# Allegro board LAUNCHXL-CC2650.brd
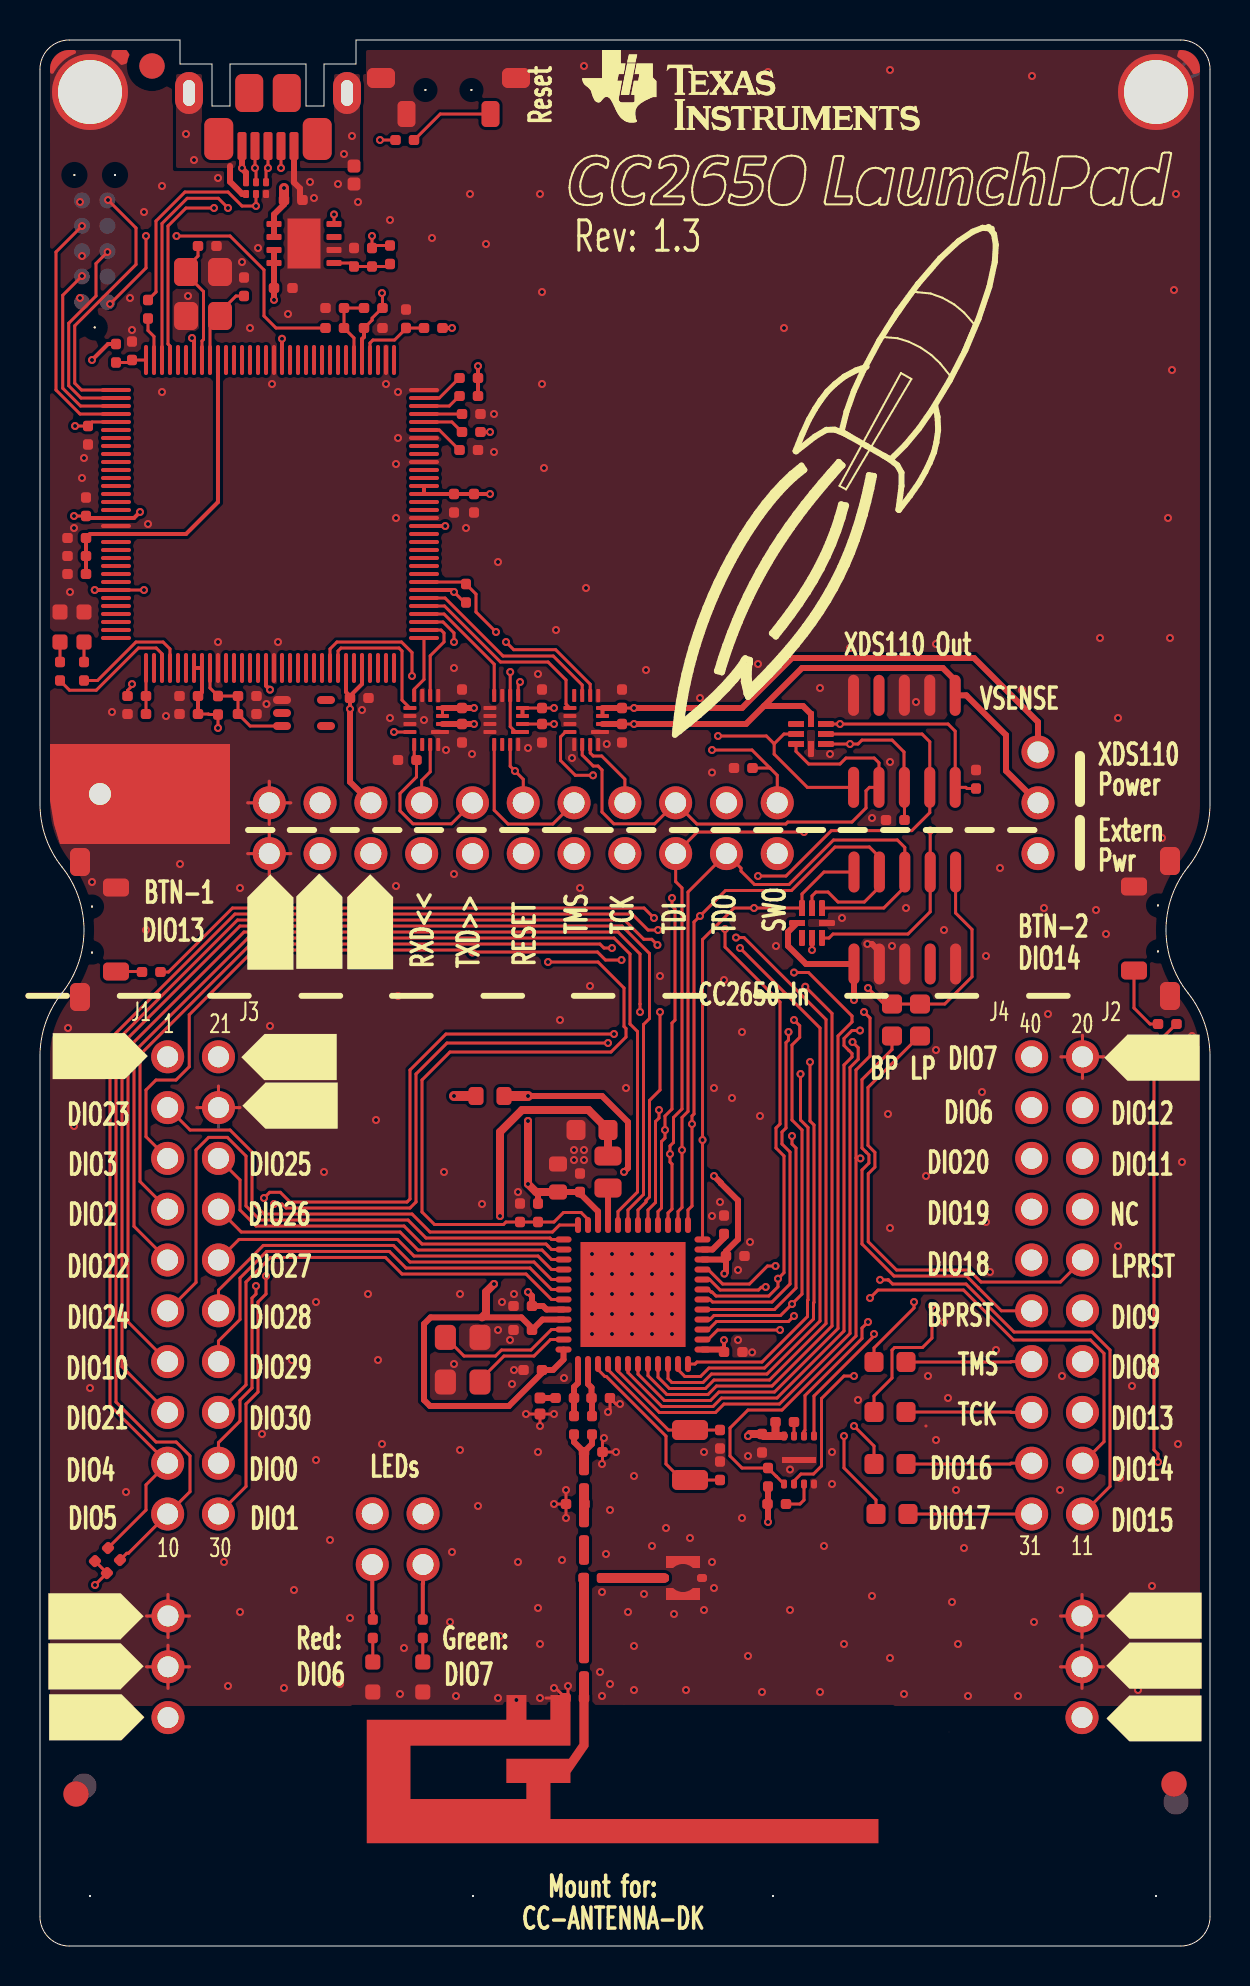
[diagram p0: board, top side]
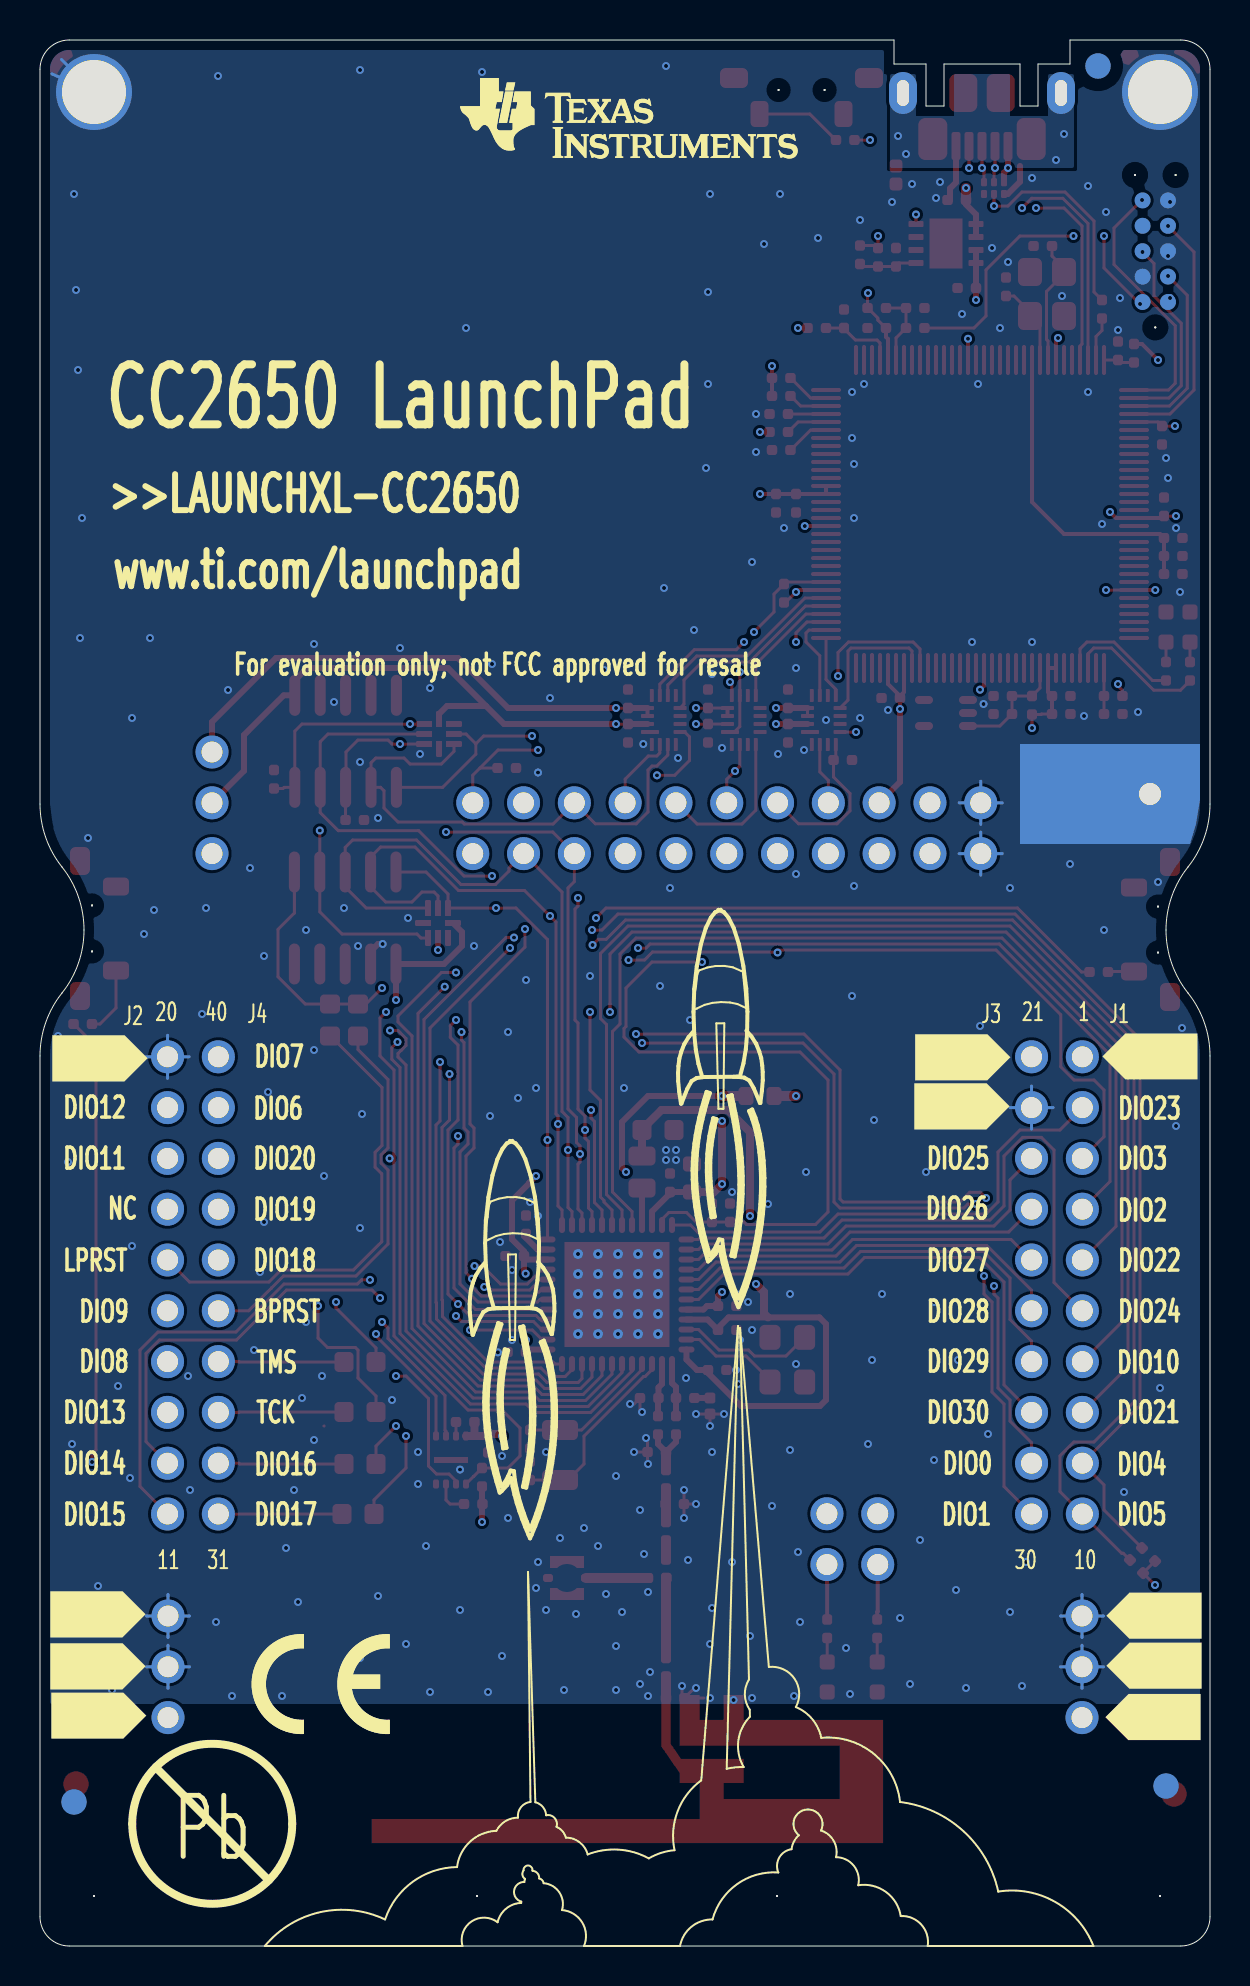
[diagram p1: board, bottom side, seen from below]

Outline 58.5 x 95.3 mm; copper layers: TOP, L2, L3, BOTTOM. Coordinates in mm from the lower left corner of the outline.
Outline path: 0,93.84 0,57.1 arc(0.28,55.43) 1.1,53.95 arc(1.92,52.47) 2.2,50.8 arc(1.92,49.13) 1.1,47.65 arc(0.28,46.17) 0,44.5 0,1.46 arc(0.43,0.43) 1.46,0 57.04,0 arc(58.07,0.43) 58.5,1.46 58.5,44.5 arc(58.22,46.17) 57.4,47.65 arc(56.58,49.13) 56.3,50.8 arc(56.58,52.47) 57.4,53.95 arc(58.22,55.43) 58.5,57.1 58.5,93.84 arc(58.07,94.87) 57.04,95.3 15.8,95.3 15.8,94.1 14.2,94.1 14.2,92 13.3,92 13.3,94.1 9.5,94.1 9.5,92 8.6,92 8.6,94.1 7,94.1 7,95.3 1.46,95.3 arc(0.43,94.87) 0,93.84

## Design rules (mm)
nets with their own width: min track width 0.15; nets CC2650_VDD GND V-SENSE VDDR VDDS XDS_VCC
nets with their own width: min track width 0.3; nets +5V

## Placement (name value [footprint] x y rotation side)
A1  2.4GHz  [ANTENNA_DN007AN]  27.2 12.3 180 top
C3  100nF  [CAPC1005X60B2N]  34.2 29.7 0 top
C4  100nF  [CAPC1005X60B2N]  34.3 34.5 0 top
C5  100nF  [CAPC1005X60B2N]  24.6 32 180 top
C6  10uF  [CAPC1608X90N#2]  25.9 37.7 90 top
C7  100nF  [CAPC1005X60B2N]  27 37.7 90 top
C8  10uF  [CAPC1608X90N]  28.4 40.8 180 top
C9  100nF  [CAPC1005X60B2N]  25.1 28.8 180 top
C11  1pF  [CAPC1005X60B2N]  26.7 26.5 270 top
C12  DNM_0402  [CAPC1005X60B2N]  27.2 24.7 0 top
C13  1pF  [CAPC1005X60B2N]  26.3 22.1 0 top
C15  DNM_0402  [CAPC1005X60B2N]  27.2 12.4 180 top
C16  100nF  [CAPC1005X60B2N]  24.6 30.8 180 top
C17  12pF  [CAPC1005X60B2N]  34 23.3 90 top
C18  12pF  [CAPC1005X60B2N]  34 25.8 270 top
C19  1uF  [CAPC1005X60B2N]  34.2 35.6 90 top
C20  100nF  [CAPC1005X60B2N]  24 36.2 90 top
C21  1pF  [CAPC1005X60B2N]  28.5 27.4 180 top
C24  12pF  [CAPC1005X60B2N]  27.2 18.4 90 top
C30  100nF  [CAPC1005X60B2N]  36.1 25.6 270 top
C31  6.8pF  [CAPC1005X60N]  25 27.4 270 top
C32  100nF  [CAPC1005X60B2N]  9.9 62.5 0 top
C33  12pF  [CAPC1005X60B2N]  10.2 82.5 90 top
C34  12pF  [CAPC1005X60B2N]  7.9 85 0 top
C35  10nF  [CAPC1005X60B2N]  15.5 62.4 0 top
C36  10nF  [CAPC1005X60B2N]  2.3 71.5 90 top
C37  10nF  [CAPC1005X60B2N]  2.4 76 270 top
C38  100nF  [CAPC1005X60B2N]  16.2 80.9 0 top
C39  100nF  [CAPC1005X60B2N]  20.7 72.6 270 top
C40  1uF  [CAPC1005X60B2N]  21.7 72.6 270 top
C41  10nF  [CAPC1005X60B2N]  7.9 62.5 180 top
C42  1uF  [CAPC1005X60B2N]  7.9 61.6 180 top
C43  100nF  [CAPC1005X60B2N]  2.3 70.4 180 top
C44  1uF  [CAPC1005X60B2N]  2.3 69.5 180 top
C45  2.2uF  [CAPC1005X60B2N]  2.3 68.6 180 top
C46  100nF  [CAPC1005X60B2N]  18.3 80.9 90 top
C47  15pF  [CAPC1005X60B2N]  16.6 84.9 270 top
C48  2.2uF  [CAPC1005X60B2N]  12.2 87.3 0 top
C49  2.2uF  [CAPC1005X60B2N]  11.7 82.9 0 top
C50  10nF  [CAPC1005X60B2N]  9.9 61.6 0 top
C51  1.8pF  [CAPC1005X60B2N]  27.2 14.4 270 top
C52  100nF  [CAPC1005X60B2N]  21.1 61.9 90 top
C53  100nF  [CAPC1005X60B2N]  21.1 61.1 270 top
C54  100nF  [CAPC1005X60B2N]  25.1 61.9 90 top
C55  100nF  [CAPC1005X60B2N]  25.1 61.1 270 top
C56  100nF  [CAPC1005X60B2N]  29.1 61.9 90 top
C57  100nF  [CAPC1005X60B2N]  29.1 61.1 270 top
C58  DNM_0402  [CAPC1005X60B2N]  28.1 18.4 180 top
C59  10nF  [CAPC1005X60B2N]  4.6 79.3 90 top
CR1  LPL296-J2L2-25  [LEDC1707X65L]  19.14 12.7 90 top
CR2  LS L296-P2Q2-1  [LEDC1708X67L]  16.64 12.7 90 top
CR4  LS L296-P2Q2-1  [LEDC1708X67L]  1 66.7 270 top
CR5  LPL296-J2L2-25  [LEDC1707X65L]  2.2 66.7 270 top
CR6  TPD4E004DRY  [SON50P100X145X60-6N]  10.3 87.6 0 top
CR7  TPD6E004RSER  [QFN50P150X150X60-8N]  37.8 61.1 270 top
CR8  TPD6E004RSER  [QFN50P150X150X60-8N]  38.1 50.4 0 top
FIDU1  FIDU_1.27mm  [FID127X142]  5.6 94 0 top
FIDU2  FIDU_1.27mm  [FID127X142]  1.8 7.6 0 top
FIDU3  FIDU_1.27mm  [FID127X142]  56.7 8.1 0 top
FIDU4  FIDU_1.27mm  [FID127X142]  5.6 94 180 bottom
FIDU5  FIDU_1.27mm  [FID127X142]  2.2 8 180 bottom
FIDU6  FIDU_1.27mm  [FID127X142]  56.8 7.2 180 bottom
FL1  BLM18HE152SN1  [FIL_BLM18HE152SN1DL]  23.2 42.5 180 top
J1  SSQ-110-23-L-D  [SAMTEC_SSQ11023LD_A2B]  6.38 44.46 0 bottom
J2  SSQ-110-23-L-D  [SAMTEC_SSQ11023LD_A2B]  49.58 44.46 0 bottom
J6  105164-0001  [MOLEX_1051640001_A2N]  10.1 90 0 top
L1  10uH  [INDC2012X150L]  28.4 37.9 90 top
L11  2.4nH  [INDC1005X60B2N]  26.7 27.4 180 top
L12  2nH  [INDC1005X60B2N]  27.2 23.8 270 top
L13  2nH  [INDC1005X60B2N]  27.2 21.2 270 top
L21  2.4nH  [INDC1005X60B2N]  27.6 26.5 270 top
LBL1  NON_COMPONENT_LABEL_8mm  [LABEL_PB-FREE_8MM_A2N]  54.1 1.9 180 bottom
LBL2  CE_label  [CE_LABEL]  45.3 10.6 180 bottom
MH1  HOLE_3.2mm_NPL  [MTG320]  2.5 2.5 0 top
MH2  HOLE_3.2mm_NPL  [MTG320]  55.8 2.5 0 top
MH3  HOLE_3.2mm_PTH  [MTG320_380]  2.5 92.7 0 top
MH4  HOLE_3.2mm_PTH  [MTG320_380]  55.8 92.7 0 top
MH5  HOLE_1.1mm_PTH  [MTG110_170]  3 57.6 0 top
NOREF  -  []  -1.9 11.6 0 top
NOREF#2  -  []  0 79.15 0 top
NOREF#3  #VALUE  [unnamed#2]  21.65 2.5 0 top
NOREF#4  -  []  51.6 11.6 0 top
NOREF#5  -  []  8.4 39.6 0 top
NOREF#6  -  []  -2 8.9 0 top
NOREF#7  -  []  8.4 41.9 0 top
NOREF#8  -  []  -1.9 14.1 0 top
NOREF#9  -  []  51.5 42 0 top
NOREF#10  -  []  40.01 0 90 top
NOREF#11  -  []  -4.3 43.3 0 top
NOREF#12  -  []  53.1 10 0 top
NOREF#13  -  []  16.5 46.4 90 top
NOREF#14  -  []  13.9 46.5 90 top
NOREF#15  -  []  17.7 43.9 90 top
NOREF#16  -  []  51.6 14.1 0 top
NOREF#17  -  []  60.3 14.2 180 bottom
NOREF#18  -  []  6.9 8.9 180 bottom
NOREF#19  -  []  58 10.3 180 bottom
NOREF#20  -  []  6.9 11.6 180 bottom
NOREF#21  -  []  51.53 65.52 180 bottom
NOREF#22  -  []  6.9 14.1 180 bottom
NOREF#23  -  []  5.6 43.1 180 bottom
NOREF#24  -  []  17.2 41.9 180 bottom
NOREF#25  -  []  60.2 42 180 bottom
NOREF#26  -  []  17.1 39.6 180 bottom
NOREF#27  -  []  60.3 11.6 180 bottom
P1  BB02-HC031-KB1-603000  [GRADCONN_BB02HC031KB1603000_A2B]  52.1 11.42 90 top
P2  BB02-HC031-KB1-603000  [GRADCONN_BB02HC031KB1603000_A2B]  6.4 11.42 90 top
P4  BB02-HJ221-KB1-603000  [GRADCONN_BB02HJ221KB160300_A2B]  36.86 57.16 180 top
P5  FTSH-105-01-F-DV-K  [SAMTEC_FTSH-105-01-F-DV-K-10L]  40.7 49.1 0 top
P6  BB02-HJ041-KB1-603000  [GRADCONN_BB02HJ041KB1603000_A2B]  16.61 19.07 0 top
P7  FTSH-105-01-F-DV-K  [SAMTEC_FTSH-105-01-F-DV-K-10L]  45.76 62.53 180 top
P8  TC2050-IDC-NL  [TAGCONNECT_TC2050IDCNLN]  2.1 82.2 90 bottom
P10  BB02-HC031-KB1-603000  [GRADCONN_BB02HC031KB1603000_A2B]  49.9 59.7 270 top
P11  MM5829-2700  [MURATA_MM58292700RJ4_A2N]  31.2 18.4 0 top
R1  100k  [RESC1005X40B2N]  24.9 36.2 90 top
R2  3.3k  [RESC1005X40B2N]  3.4 19.9 225 top
R3  3.3k  [RESC1005X40B2N]  4 19.3 225 top
R11  2.2k  [RESC1005X40B2N]  36.4 23.9 270 top
R14  220  [RESC1005X40B2N]  16.64 15.4 90 top
R15  180  [RESC1005X40B2N]  19.14 15.4 90 top
R17  10k  [RESC1005X40B2N]  16.2 81.9 0 top
R18  4.7k  [RESC1005X40B2N]  8.9 62.5 270 top
R20  100  [RESC1005X40B2N]  15.2 80.9 180 top
R21  DNM  [RESC1005X40B2N]  15.2 81.9 180 top
R22  330k  [RESC1005X40B2N]  5.3 62.5 180 top
R23  180  [RESC1005X40B2N]  1 64.2 270 top
R24  220k  [RESC1005X40B2N]  5.3 61.6 180 top
R25  220  [RESC1005X40B2N]  2.2 64.2 270 top
R27  1k  [RESC1005X40B2N]  21.9 77.5 180 top
R28  4.87k  [RESC1005X40B2N]  21.9 74.8 180 top
R29  1k  [RESC1005X40B2N]  21.1 76.6 0 top
R30  1k  [RESC1005X40B2N]  21.1 75.7 0 top
R31  51  [RESC1005X40B2N]  19.2 80.9 0 top
R32  33k  [RESC1005X40N]  15.7 88.1 90 top
R33  51k  [RESC1005X40B2N]  17.5 84.1 90 top
R34  30k  [RESC1005X40B2N]  15.7 84.9 270 top
R39  1k  [RESC1005X40B2N]  21.9 78.4 180 top
R46  DNM  [RESC1608X55N]  43.3 29.2 180 top
R47  DNM  [RESC1608X55N]  43.3 26.7 180 top
R48  DNM  [RESC1608X55N]  43.3 24.1 180 top
R49  DNM  [RESC1608X55N]  43.4 21.6 180 top
R51  DNM  [RESC1608X55N]  44 45.5 90 top
R52  0  [RESC1608X55N]  42.6 47.1 270 top
R55  100  [RESC1005X40B2N]  55.9 46.1 0 top
R56  100  [RESC1005X40B2N]  5.1 48.7 0 top
R57  100  [RESC1005X40B2N]  18.7 90.3 180 top
R58  3.3k  [RESC1005X40B2N]  21.3 68.1 270 top
R59  DNM  [RESC1005X40B2N]  37.3 22.1 180 top
R60  DNM  [RESC1005X40B2N]  37.7 26.2 180 top
R61  100k  [RESC1005X40B2N]  17.9 59.3 0 top
R62  100k  [RESC1005X40B2N]  34.7 58.9 0 top
R63  100k  [RESC1005X40B2N]  42.3 56.3 0 top
R65  100k  [RESC1005X40B2N]  46.8 58.8 270 top
R66  100  [RESC1005X40B2N]  3.8 80.1 270 top
R67  DNM  [RESC1005X40B2N]  5.4 82.3 270 top
SW1  1188E-1K2-V  [SW_1188E1K2V_A2N]  2 54.2 270 top
SW2  1188E-1K2-V  [SW_1188E1K2V_A2N]  56.5 47.5 90 top
SW3  1188E-1K2-V  [SW_1188E1K2V_A2N]  23.8 93.4 180 top
U1  CC2650F128RGZ  [QFNFC50P700X700X80-49CL]  26.9 29.1 0 top
U4  MX25R8035FZUIL0  [SON50P300X200X60-9B2L]  37.2 23.1 0 top
U5  TM4C1294NCPDTT3R  [QFP40P1600X1600X120-128N]  5.3 63.9 0 top
U6  LM4040B25IDCK  [SOT65P210X110-5N]  12.1 62.3 270 top
U7  TPS79601DR  [SON65P300X300X100-9AL]  11.7 86.1 270 top
U8  SN74AVC4T245RSV  [QFNFC40P180X260X55-16A2L]  20 60.7 90 top
U9  SN74AVC4T245RSV  [QFNFC40P180X260X55-16A2L]  28 60.7 90 top
U10  SN74AVC4T245RSV  [QFNFC40P180X260X55-16A2L]  24 60.7 90 top
UNK#REFDES  -  []  28.1 94.8 0 top
UNK#REFDES#2  -  []  36.5 93.4 180 bottom
Y1  32.768kHz  [XTAL_FC-135N]  32.5 23.3 90 top
Y2  24MHz  [OSCCC250X320X60-4L]  22 28.2 90 top
Y3  16MHz  [OSCCC250X320X100-4BN]  9 81.5 90 top

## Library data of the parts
A1 = ANTENNA_DN007
C3-C5 C7 C9 C11-C13 C15-C21 C24 C30 C32-C50 C52-C59 = CAPACITOR: User Part Number: #PN
C6 C8 = CAPACITOR: alternate symbols: (CAPC1608X90L,CAPC1608X90M)
C31 = CAPACITOR: alternate symbols: (CAPC1005X60L,CAPC1005X60M)
C51 = CAPACITOR_HOR: User Part Number: #PN
CR1 CR5 = LED: alternate symbols: (LEDC1707X65L,LEDC1707X65M)
CR2 CR4 = LED: alternate symbols: (LEDC1708X67L,LEDC1708X67M)
CR6 = DIODE_TPD4E004_SON6: User Part Number: #PN; alternate symbols: (SON50P100X145X65-6L,SON50P100X145X65-6M)
CR7 CR8 = DIODE_TVS_TPD6E004_QFN8_V1_0: alternate symbols: (QFN50P150X150X60-8L,QFN50P150X150X60-8M,QFN50P150X150X60-8AL)
FIDU1-FIDU6 = FIDMARK
FL1 = FILTER_2PIN: alternate symbols: (FIL_BLM18HE152SN1DL,FIL_BLM18HE152SN1DM)
J1 J2 = CONN_HEADER_2X10_J_S_V1: User Part Number: #PN; alternate symbols: (SAMTEC_SSQ11023LD_A2C,SAMTEC_SSQ11023LD_A2A)
J6 = CONN_USB_MICRO_B_2MH: User Part Number: #PN; alternate symbols: (MOLEX_1051640001_A2L,MOLEX_1051640001_A2M)
L1 = INDUCTOR: alternate symbols: (INDC2012X150L,INDC2012X150M)
L11-L13 L21 = INDUCTOR: User Part Number: #PN
LBL1 = LABEL_Pb-free_V1: User Part Number: #PN
LBL2 = CE_LABEL
MH1 MH2 = HOLE_NPL
MH3-MH5 = HOLE_PTH
NOREF#3 = -: User Part Number: #PN
P1 P2 P10 = CONN_HEADER_3_P_S: User Part Number: #PN; alternate symbols: (GRADCONN_BB02HC031KB1603000_A2C,GRADCONN_BB02HC031KB1603000_A2A)
P4 = CONN_HEADER_2X11_P_S: User Part Number: #PN; alternate symbols: (GRADCONN_BB02HJ221KB160300_A2C,GRADCONN_BB02HJ221KB160300_A2A)
P5 P7 = CONN_HEADER_2X5: alternate symbols: (SAMTEC_FTSH-105-01-F-DV-K-10L,SAMTEC_FTSH-105-01-F-DV-K-10M)
P6 = CONN_HEADER_2X2_P: User Part Number: #PN; alternate symbols: (GRADCONN_BB02HJ041KB1603000_A2C,GRADCONN_BB02HJ041KB1603000_A2A)
P8 = CONN_IDC_TC2050-IDC-NL: User Part Number: #PN; alternate symbols: (TAGCONNECT_TC2050IDCNLL,TAGCONNECT_TC2050IDCNLM)
P11 = CONN_COAX_1_1_P_2MH_V1: User Part Number: #PN; alternate symbols: (MURATA_MM58292700RJ4_A2L,MURATA_MM58292700RJ4_A2M)
R1-R3 R11 R14 R15 R17 R18 R20-R25 R27-R31 R33 R34 R39 R55-R63 R65-R67 = RESISTOR: User Part Number: #PN
R32 = RESISTOR: alternate symbols: (RESC1005X40L,RESC1005X40M)
R46-R49 R51 R52 = RESISTOR: alternate symbols: (RESC1608X55L,RESC1608X55M)
SW1-SW3 = SWITCH_TACT_V2: alternate symbols: (SW_1188E1K2V_A2L,SW_1188E1K2V_A2M)
U1 = IC_RF_CC26XX_QFN48_V2: alternate symbols: (QFNFC50P700X700X80-49CL,QFNFC50P700X700X80-49CM)
U4 = IC_FLASH_MX25R8035F_USON8: User Part Number: #PN; alternate symbols: (SON50P300X200X60-9B2L,SON50P300X200X60-9B2M)
U5 = IC_PROC_TM4C1294NCPDT_TQFP128: alternate symbols: (QFP40P1600X1600X120-128L,QFP40P1600X1600X120-128M)
U6 = IC_REF_LM4040_SC70-5: alternate symbols: (SOT65P210X110-5L,SOT65P210X110-5M)
U7 = IC_PM_TPS79601_SON8: alternate symbols: (SON65P300X300X100-9AL,SON65P300X300X100-9AM)
U8-U10 = IC_XCVR_SN74AVC4T245_UQFN16_2: User Part Number: #PN; alternate symbols: (QFNFC40P180X260X55-16A2L,QFNFC40P180X260X55-16A2M)
Y1 = CRYSTAL: alternate symbols: (XTAL_FC-135L,XTAL_FC-135M)
Y2 = XTAL_4PIN_S: alternate symbols: (OSCCC250X320X60-4L,OSCCC250X320X60-4M)
Y3 = XTAL_4: alternate symbols: (OSCCC250X320X100-4BL,OSCCC250X320X100-4BM)

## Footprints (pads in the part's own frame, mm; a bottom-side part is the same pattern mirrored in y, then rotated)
ANTENNA_DN007AN
  rect 0.46x0.5 smd: 1(0,0)
  rect 1.001x0.5 smd: 2(1.18,0) 3(3.38,0)
CAPC1005X60B2N
  custom 0.125x0.125 smd: 1(0,0) 2(0.924,0)
CAPC1005X60N
  custom 0.135x0.135 smd: 1(0,0) 2(0.8,0)
CAPC1608X90N
  custom 0.237x0.237 smd: 1(0,0) 2(1.6,0)
CAPC1608X90N#2
  custom 0.188x0.188 smd: 1(0,0) 2(1.4,0)
CE_LABEL
  oval 0.025x0.051 smd: 1(-0.15,0.1)
FID127X142
  round 1.27 smd: 1(0,0)
FIL_BLM18HE152SN1DL
  custom 0.188x0.188 smd: 1(0,0) 2(1.4,0)
GRADCONN_BB02HC031KB1603000_A2B
  round 1.65 hole 1.05: 1(0,0) 2(2.54,0) 3(5.08,0)
GRADCONN_BB02HJ041KB1603000_A2B
  round 1.65 hole 1.05: 1(0,0) 2(0,2.54) 3(2.54,0) 4(2.54,2.54)
GRADCONN_BB02HJ221KB160300_A2B
  round 1.65 hole 1.05: 1(0,0) 2(0,2.54) 3(2.54,0) 4(2.54,2.54) 5(5.08,0) 6(5.08,2.54) 7(7.62,0) 8(7.62,2.54) 9(10.16,0) 10(10.16,2.54) 11(12.7,0) 12(12.7,2.54) 13(15.24,0) 14(15.24,2.54) 15(17.78,0) 16(17.78,2.54) 17(20.32,0) 18(20.32,2.54) 19(22.86,0) 20(22.86,2.54) 21(25.4,0) 22(25.4,2.54)
INDC1005X60B2N
  custom 0.125x0.125 smd: 1(0,0) 2(0.924,0)
INDC2012X150L
  custom 0.237x0.237 smd: 1(0,0) 2(1.6,0)
LEDC1707X65L
  custom 0.188x0.188 smd: 1(0,0) 2(1.501,0)
LEDC1708X67L
  custom 0.188x0.188 smd: 1(0,0) 2(1.501,0)
MOLEX_1051640001_A2N
  custom 0.362x0.362 smd: (-1.162,0.35) (3.762,0.35)
  custom 0.35x0.35 smd: (0.362,2.65) (2.238,2.65)
  custom 0.113x0.113 smd: 1(0,0) 2(0.65,0) 3(1.3,0) 4(1.95,0) 5(2.6,0)
  oval 1.4x2.1 hole 0.6x1.3: M1(-2.65,2.65) M2(5.25,2.65)
MTG110_170
  round 1.699 hole 1.1: 1(0,0)
MTG320
  round 0.099 hole 3.2 unplated: (0,0)
MTG320_380
  round 3.8 hole 3.2: 1(0,0)
MURATA_MM58292700RJ4_A2N
  custom 0.1x0.1 smd: 1(0,0) 2(1.9,0)
  custom 0.15x0.15 smd: M1(0.95,-0.8) M2(0.95,0.8)
OSCCC250X320X60-4L
  custom 0.263x0.263 smd: 1(0,0) 2(2.23,0) 3(2.23,1.73) 4(0,1.73)
OSCCC250X320X100-4BN
  custom 0.299x0.299 smd: 1(0,0) 2(2.2,0) 3(2.2,1.699) 4(0,1.699)
QFN50P150X150X60-8N
  custom 0.075x0.075 smd: 1(0,0) 2(0.5,0) 3(1,0) 4(1.25,0.75) 5(1,1.5) 6(0.5,1.5) 7(0,1.5) 8(-0.25,0.75)
QFNFC40P180X260X55-16A2L
  custom 0.05x0.05 smd: 1(0,0) 2(0.4,-0.125) 3(0.8,-0.125) 4(1.2,-0.125) 5(1.825,0.09) 6(1.825,0.49) 7(1.825,0.89) 8(1.825,1.29) 9(1.2,1.505) 10(0.8,1.505) 11(0.4,1.505) 12(0,1.505) 13(-0.625,1.29) 14(-0.625,0.89) 15(-0.625,0.49) 16(-0.625,0.09)
QFNFC50P700X700X80-49CL
  oval 0.3x0.8 smd: 1(0,0) 2(0.5,0) 3(1.001,0) 4(1.501,0) 5(1.999,0) 6(2.499,0) 7(3,0) 8(3.5,0) 9(4,0) 10(4.501,0) 11(5.001,0) 12(5.499,0) 25(5.499,6.949) 26(5.001,6.949) 27(4.501,6.949) 28(4,6.949) 29(3.5,6.949) 30(3,6.949) 31(2.499,6.949) 32(1.999,6.949) 33(1.501,6.949) 34(1.001,6.949) 35(0.5,6.949) 36(0,6.949)
  oval 0.8x0.3 smd: 13(6.226,0.724) 14(6.226,1.224) 15(6.226,1.725) 16(6.226,2.225) 17(6.226,2.725) 18(6.226,3.226) 19(6.226,3.726) 20(6.226,4.224) 21(6.226,4.724) 22(6.226,5.225) 23(6.226,5.725) 24(6.226,6.226) 37(-0.724,6.226) 38(-0.724,5.725) 39(-0.724,5.225) 40(-0.724,4.724) 41(-0.724,4.224) 42(-0.724,3.726) 43(-0.724,3.226) 44(-0.724,2.725) 45(-0.724,2.225) 46(-0.724,1.725) 47(-0.724,1.224) 48(-0.724,0.724)
  rect 5.25x5.25 smd: 49(2.751,3.475)
QFP40P1600X1600X120-128N
  oval 0.201x1.501 smd: 1(0,0) 2(0.399,0) 3(0.8,0) 4(1.199,0) 5(1.6,0) 6(1.999,0) 7(2.4,0) 8(2.799,0) 9(3.2,0) 10(3.599,0) 11(4,0) 12(4.399,0) 13(4.801,0) 14(5.199,0) 15(5.601,0) 16(6,0) 17(6.401,0) 18(6.8,0) 19(7.201,0) 20(7.6,0) 21(8.001,0) 22(8.4,0) 23(8.801,0) 24(9.2,0) 25(9.601,0) 26(10,0) 27(10.399,0) 28(10.8,0) 29(11.199,0) 30(11.6,0) 31(11.999,0) 32(12.4,0) 65(12.4,15.4) 66(11.999,15.4) 67(11.6,15.4) 68(11.199,15.4) 69(10.8,15.4) 70(10.399,15.4) 71(10,15.4) 72(9.601,15.4) 73(9.2,15.4) 74(8.801,15.4) 75(8.4,15.4) 76(8.001,15.4) 77(7.6,15.4) 78(7.201,15.4) 79(6.8,15.4) 80(6.401,15.4) 81(6,15.4) 82(5.601,15.4) 83(5.199,15.4) 84(4.801,15.4) 85(4.399,15.4) 86(4,15.4) 87(3.599,15.4) 88(3.2,15.4) 89(2.799,15.4) 90(2.4,15.4) 91(1.999,15.4) 92(1.6,15.4) 93(1.199,15.4) 94(0.8,15.4) 95(0.399,15.4) 96(0,15.4)
  oval 1.501x0.201 smd: 33(13.899,1.501) 34(13.899,1.9) 35(13.899,2.301) 36(13.899,2.7) 37(13.899,3.099) 38(13.899,3.5) 39(13.899,3.899) 40(13.899,4.3) 41(13.899,4.699) 42(13.899,5.1) 43(13.899,5.499) 44(13.899,5.9) 45(13.899,6.299) 46(13.899,6.7) 47(13.899,7.099) 48(13.899,7.501) 49(13.899,7.899) 50(13.899,8.301) 51(13.899,8.7) 52(13.899,9.101) 53(13.899,9.5) 54(13.899,9.901) 55(13.899,10.3) 56(13.899,10.701) 57(13.899,11.1) 58(13.899,11.501) 59(13.899,11.9) 60(13.899,12.301) 61(13.899,12.7) 62(13.899,13.099) 63(13.899,13.5) 64(13.899,13.899) 97(-1.501,13.899) 98(-1.501,13.5) 99(-1.501,13.099) 100(-1.501,12.7) 101(-1.501,12.301) 102(-1.501,11.9) 103(-1.501,11.501) 104(-1.501,11.1) 105(-1.501,10.701) 106(-1.501,10.3) 107(-1.501,9.901) 108(-1.501,9.5) 109(-1.501,9.101) 110(-1.501,8.7) 111(-1.501,8.301) 112(-1.501,7.899) 113(-1.501,7.501) 114(-1.501,7.099) 115(-1.501,6.7) 116(-1.501,6.299) 117(-1.501,5.9) 118(-1.501,5.499) 119(-1.501,5.1) 120(-1.501,4.699) 121(-1.501,4.3) 122(-1.501,3.899) 123(-1.501,3.5) 124(-1.501,3.099) 125(-1.501,2.7) 126(-1.501,2.301) 127(-1.501,1.9) 128(-1.501,1.501)
RESC1005X40B2N
  custom 0.125x0.125 smd: 1(0,0) 2(0.924,0)
RESC1005X40N
  custom 0.16x0.16 smd: 1(0,0) 2(0.899,0)
RESC1608X55N
  custom 0.237x0.237 smd: 1(0,0) 2(1.6,0)
SAMTEC_FTSH-105-01-F-DV-K-10L
  oval 0.551x2.05 smd: 1(0,0) 2(0,4.6) 3(1.27,0) 4(1.27,4.6) 5(2.54,0) 6(2.54,4.6) 7(3.81,0) 8(3.81,4.6) 9(5.08,0) 10(5.08,4.6)
SAMTEC_SSQ11023LD_A2B
  round 1.65 hole 1.05: 1(0,0) 2(2.54,0) 3(0,2.54) 4(2.54,2.54) 5(0,5.08) 6(2.54,5.08) 7(0,7.62) 8(2.54,7.62) 9(0,10.16) 10(2.54,10.16) 11(0,12.7) 12(2.54,12.7) 13(0,15.24) 14(2.54,15.24) 15(0,17.78) 16(2.54,17.78) 17(0,20.32) 18(2.54,20.32) 19(0,22.86) 20(2.54,22.86)
SON50P100X145X60-6N
  custom 0.075x0.075 smd: 1(0,0) 2(0.5,0) 3(1.001,0) 4(1.001,0.589) 5(0.5,0.589) 6(0,0.589)
SON50P300X200X60-9B2L
  custom 0.075x0.075 smd: 1(0,0) 2(0.5,0) 3(1,0) 4(1.5,0) 5(1.5,2.4) 6(1,2.4) 7(0.5,2.4) 8(0,2.4)
  rect 1.7x0.3 smd: 9(0.75,1.2)
SON65P300X300X100-9AL
  custom 0.075x0.075 smd: 1(0,0) 2(0.65,0) 3(1.3,0) 4(1.95,0) 5(1.95,3) 6(1.3,3) 7(0.65,3) 8(0,3)
  rect 2.5x1.65 smd: 9(0.975,1.5)
SOT65P210X110-5N
  oval 0.399x0.899 smd: 1(0,0) 2(0.65,0) 3(1.3,0) 4(1.3,2.2) 5(0,2.2)
SW_1188E1K2V_A2N
  round 0.099 hole 0.899 unplated: (2.229,0.6) (4.529,0.6)
  custom 0.25x0.25 smd: 1(0,0) 2(6.75,0)
  custom 0.225x0.225 smd: 3(1.275,1.8) 4(5.475,1.8)
TAGCONNECT_TC2050IDCNLN
  round 0.099 hole 1.001 unplated: (-1.27,0.635) (6.35,-0.38) (6.35,1.65)
  round 0.8 smd: 1(0,0) 2(1.27,0) 3(2.54,0) 4(3.81,0) 5(5.08,0) 6(5.08,1.27) 7(3.81,1.27) 8(2.54,1.27) 9(1.27,1.27) 10(0,1.27)
unnamed#2
  round 0.099 hole 3.2 unplated: (0,0) (15,0)
XTAL_FC-135N
  custom 0.25x0.25 smd: 1(0,0) 2(2.499,0)

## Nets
+5V: J1.2 P2.1 P4.20
GND: A1.2(GND_2) A1.3(GND_3) C3.2 C4.2 C5.2 C6.2 C7.2 C8.2 C9.2 C12.2 C13.1 C15.2 C16.2 C17.2 C18.2 C19.2 C20.2 C21.1 C30.2 C31.2 C32.2 C33.2 C34.2 C35.2 C36.2 C37.2 C38.2 C39.2 C40.2 C41.2 C42.2 C43.2 C44.2 C45.2 C46.2 C48.2 C49.2 C50.2 C52.2 C53.2 C54.2 C55.2 C56.2 C57.2 C59.2 CR1.1(C) CR2.1(C) CR4.1(C) CR5.1(C) CR6.3 CR7.4(GND) CR8.4(GND) J1.4 J2.2 J6.5(GND) MH3.1 MH4.1 MH5.1 P1.2 P1.3 P2.2 P2.3 P4.21 P4.22 P5.3 P5.5 P5.9 P7.3 P7.5 P7.9 P8.3(7) P8.5(8) P8.9(10) P11.2 P11.M1 P11.M2 R21.2 R24.2 R28.1 R29.2 R32.1 R34.1 R61.1 R62.1 R63.1 R65.1 SW1.1 SW1.2 SW1.3 SW2.1 SW2.2 SW2.4 SW3.1 SW3.2 SW3.4 U1.49(VSS) U4.4(GND) U4.9(EGP) U5.10(GNDA) U5.17(GND#17) U5.48(GND#48) U5.55(GND#55) U5.58(GND#58) U5.64(NWAKE) U5.66(XOSC0) U5.80(GND#80) U5.114(GND#114) U6.1(ANODE) U7.6(GND) U7.9(GND/TAB) U8.1(1NOE) U8.5(2DIR) U8.7(1A2) U8.10(GND#10) U8.11(GND#11) U8.16(2NOE) U9.1(1NOE) U9.5(2DIR) U9.10(GND#10) U9.11(GND#11) U9.13(2B1) U9.16(2NOE) U10.7(1A2) U10.9(2A2) U10.10(GND#10) U10.11(GND#11) U10.12(2B2) U10.16(2NOE) Y2.2 Y2.4 Y3.2(GND) Y3.4(NC_4)
VDDC: C43.1 C44.1 C45.1 U5.87(VDDC#87) U5.115(VDDC#115)
VDDR: C8.1 C9.1 C16.1 L1.2 U1.45(VDDR#45) U1.48(VDDR#48)
VDDS: C3.1 C4.1 C5.1 C6.1 C7.1 FL1.1 R1.2 U1.13(VDDS2) U1.22(VDDS3) U1.34(VDDS_DCDC) U1.44(VDDS)
BP_RESET: J2.11 R52.2
CC2650_RESET: C20.1 CR8.2(IO2) P4.12 P5.10 R1.1 R51.2 R52.1 U1.35(RESET_N)
CC2650_RXD: J1.7 P4.16 U1.7(DIO_2)
CC2650_SWO: J2.9 P4.2 U1.28(DIO_18)
CC2650_TCK: CR8.6(IO5) P4.8 P5.4 R47.2 U1.25(JTAG_TCKC)
CC2650_TMS: CR8.7(IO6) P4.10 P5.2 R46.2 U1.24(JTAG_TMSC)
CC2650_TXD: J1.5 P4.14 U1.8(DIO_3)
CC2650_VDD: C30.1 CR8.8(VCC) FL1.2 J1.1 P1.1 P4.18 P5.1 P10.3 R2.2 R3.2 R11.2 R59.2 R60.2 U4.8(VCC)
DCDC_SW: L1.1 U1.33(DCDC_SW)
DIO0: J1.18 U1.5(DIO_0)
DIO1: J1.20 U1.6(DIO_1)
DIO4_SCL: J1.17 R2.1 U1.9(DIO_4)
DIO5_SDA: J1.19 R3.1 U1.10(DIO_5)
DIO6_RLED: J2.3 P6.2 U1.11(DIO_6)
DIO7_GLED: J2.1 P6.4 U1.12(DIO_7)
DIO8_MISO: J2.14 U1.14(DIO_8) U4.2(SO/SIO1)
DIO9_MOSI: J2.12 U1.15(DIO_9) U4.5(SI/SIO0)
DIO10_SCLK: J1.13 U1.16(DIO_10) U4.6(SCLK)
DIO11_CS: J2.6 U1.17(DIO_11)
DIO12: J2.4 U1.18(DIO_12)
DIO13_BTN1: J2.16 R56.2 U1.19(DIO_13)
DIO14_BTN2: J2.18 R55.2 U1.20(DIO_14)
DIO15: J2.20 U1.21(DIO_15)
DIO16_TDO: CR8.5(IO4) P4.4 P5.6 R48.2 U1.26(DIO_16)
DIO17_TDI: CR8.3(IO3) P4.6 P5.8 R49.2 U1.27(DIO_17)
DIO19_CTS: J2.7 U1.29(DIO_19)
DIO20_FLASH_CS: J2.5 R11.1 U1.30(DIO_20) U4.1(NCS)
DIO21: J1.15 U1.31(DIO_21)
DIO22: J1.9 U1.32(DIO_22)
DIO23_ANALOG: J1.3 U1.36(DIO_23)
DIO24_ANALOG: J1.11 U1.37(DIO_24)
DIO25_ANALOG: J1.6 U1.38(DIO_25)
DIO26_ANALOG: J1.8 U1.39(DIO_26)
DIO27_ANALOG: J1.10 U1.40(DIO_27)
DIO28_ANALOG: J1.12 U1.41(DIO_28)
DIO29_ANALOG: J1.14 U1.42(DIO_29)
DIO30_ANALOG: J1.16 U1.43(DIO_30)
IRSTN: P8.10(5) R20.2
ITCK: P8.4(2) U5.100(PC0/TCK/SWCLK)
ITDI: P8.8(4) U5.98(PC2/TDI)
ITDO: P8.6(3) U5.97(PC3/TDO/SWO)
ITMS: P8.2(1) U5.99(PC1/TMS/SWDIO)
LP_RESET: J2.10 R51.1
USB_DM: CR6.5 J6.2(D-) U5.93(PL7/USB0DM)
USB_DP: CR6.4 J6.3(D+) U5.94(PL6/USB0DP)
USB_ID: CR6.2 J6.4(ID) R67.1
USB_VBUS: C48.1 CR6.6 J6.1(VCC) P4.19 R22.2 R66.1 U7.1(IN#1) U7.2(IN#2) U7.8(EN)
V-SENSE: C53.1 C55.1 C57.1 CR7.8(VCC) P7.1 P10.2 U8.2(VCCB) U9.2(VCCB) U10.2(VCCB)
XDS_RESET: R58.1 U5.40(PA6) U10.1(1NOE) U10.6(1A1)
XDS_RESET_LS: CR7.2(IO2) P4.11 P7.10 R57.2 U10.15(1B1)
XDS_RX: U5.33(PA0/U0RX) U8.8(2A1)
XDS_RX_LS: P4.13 R61.2 U8.13(2B1)
XDS_SWO: U5.25(PC4/C1-) U8.9(2A2)
XDS_SWO_LS: P4.1 R62.2 U8.12(2B2)
XDS_TCK: U5.35(PA2/SSI0CLK) U9.6(1A1)
XDS_TCK_LS: CR7.6(IO5) P4.7 P7.4 U9.15(1B1)
XDS_TDI: U5.38(PA5/SSI0XDAT1) U9.7(1A2)
XDS_TDI_LS: CR7.3(IO3) P4.5 P7.8 U9.14(1B2)
XDS_TDO: U5.37(PA4/SSI0XDAT0) U9.9(2A2)
XDS_TDO_LS: CR7.5(IO4) P4.3 P7.6 R63.2 U9.12(2B2)
XDS_TMS: U5.36(PA3/SSI0FSS) U10.8(2A1)
XDS_TMS_DIR: U5.24(PC5/C1+) U10.5(2DIR)
XDS_TMS_LS: CR7.7(IO6) P4.9 P7.2 R65.2 U10.13(2B1)
XDS_TX: U5.34(PA1/U0TX) U8.6(1A1)
XDS_TX_LS: P4.15 U8.15(1B1)
XDS_VCC: C35.1 C36.1 C37.1 C38.1 C39.1 C40.1 C41.1 C42.1 C47.1 C49.1 C52.1 C54.1 C56.1 P4.17 P8.1(6) P10.1 R17.2 R18.2 R27.1 R30.2 R31.2 R33.2 R39.1 R58.2 U5.7(VDD#7) U5.8(VDDA) U5.16(VDD#16) U5.26(VDD#26) U5.28(VDD#28) U5.39(VDD#39) U5.47(VDD#47) U5.51(VDD#51) U5.52(VDD#52) U5.69(VDD#69) U5.79(VDD#79) U5.90(VDD#90) U5.101(VDD#101) U5.113(VDD#113) U5.122(VDD#122) U7.3(OUT#3) U7.4(OUT#4) U8.3(VCCA) U8.4(1DIR) U9.3(VCCA) U9.4(1DIR) U10.3(VCCA) U10.4(1DIR)
N949215: R17.1 R20.1 R21.1 U5.70(NRST)
N949243: R30.1 U5.60(PK7)
N949263: C47.2 R33.1 R34.2 U7.5(FB)
N949375: R28.2 U5.59(RBIAS)
N949517: R22.1 R24.1 U5.1(PD0/AIN15)
N949687: C34.1 U5.89(OSC1) Y3.3
N949695: C33.1 U5.88(OSC0) Y3.1
N950083: C32.1 C50.1 R18.1 U5.9(VREFA+) U6.3(CATHODE)
N950235: R67.2 U5.95(PB0/USB0ID)
N951001: R39.2 U5.63(PK4)
N951013: R29.1 U5.61(PK6)
N951017: R27.2 U5.62(PK5)
N952443: C46.1 R31.1 U5.68(VBAT)
N1004371: R23.2 U5.3(PD2/AIN13)
N1004534: R25.2 U5.4(PD3/AIN12)
N1013277: U1.46(X24M_N) Y2.3
N1013851: C21.2 L21.1 U1.2(RF_N)
N1013859: C11.1 L11.1 U1.1(RF_P)
N1013883: C31.1 L11.2
N1013899: C11.2 C12.1 L12.1 L21.2
N1013927: C13.2 L12.2 L13.1
N1013977: A1.1(FEED_1) C15.1 C51.2
N1014081: C19.1 U1.23(DCOUPL)
N1014101: C17.1 U1.3(X32K_Q1) Y1.1
N1014113: C18.1 U1.4(X32K_Q2) Y1.2
N1014125: C24.1 C51.1 C58.2
N1014335: C24.2 L13.2
N1018937: U1.47(X24M_P) Y2.1
N1031635: CR6.1 J6.M1(SHIELD1) J6.M2(SHIELD2) R32.2
N1105722: CR1.2(A) R15.1
N1105771: CR2.2(A) R14.1
N1105824: P6.1 R14.2
N1106228: P6.3 R15.2
N1176544: J2.13 R46.1
N1176548: J2.15 R47.1
N1176568: J2.17 R48.1
N1177007: J2.19 R49.1
N1288065: R55.1 SW2.3
N1288098: R56.1 SW1.4
N1384129: R57.1 SW3.3
N1409884: R59.1 U4.3(NWP/SIO2)
N1409917: R60.1 U4.7(NRST/SIO3)
N1429173: C58.1 P11.1
N1432281: C59.1 R66.2 U5.96(PB1/USB0VBUS)
N10367920: CR5.2(A) R25.1
N10368080: CR4.2(A) R23.1

Pads without a net: CR7 1; CR8 1; FIDU1 1; FIDU2 1; FIDU3 1; FIDU4 1; FIDU5 1; FIDU6 1; J2 8; LBL2 1; P5 7; P7 7; P8 7; U5 2 5 6 11 12 13 14 15 18 19 20 21 22 23 27 29 30 31 32 41 42 43 44 45 46 49 50 53 54 56 57 65 67 71 72 73 74 75 76 77 78 81 82 83 84 85 86 91 92 102 103 104 105 106 107 108 109 110 111 112 116 117 118 119 120 121 123 124 125 126 127 128; U6 2 4 5; U7 7; U8 14; U9 8; U10 14

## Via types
v1: diameter 0.4, hole 0.2, TOP to BOTTOM, 386 vias
v2: diameter 0.5, hole 0.201, TOP to BOTTOM, 25 vias

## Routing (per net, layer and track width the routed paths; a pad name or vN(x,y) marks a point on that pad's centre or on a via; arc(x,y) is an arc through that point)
+5V: length 55.4
  L3 w0.5: P2.1 0.8,17.02 0.8,41.9 4.7,45.8 7.58,45.8 J1.2 14,49.54 P4.20
GND: length 133
  TOP w0.15: 26.12,12.4 A1.2 ; 26.12,12.4 25.3,12.4 ; 26.12,12.4 C15.2 ; v1(26.4,13) 26.4,12.52 C15.2 ; 52.1,12.88 P1.2 ; P1.2 51.02,13.96 ; P1.2 52.1,15.04 ; P1.2 53.18,13.96 ; J1.4 10,41.92 ; J1.4 8.92,43 ; J1.4 7.85,41.92 ; 25.79,22.1 C13.1 ; C13.1 26.3,22.6 ; C13.1 v1(26.3,21.4) ; P2.2 7.48,13.96 ; P2.2 5.32,13.96 ; P2.2 6.4,15.04 ; P2.2 6.4,12.88 ; 11.46,56.08 P4.21 ; P4.21 12.54,57.16 ; P4.21 11.46,58.24 ; P4.21 10.39,57.16 ; P1.3 52.1,17.58 ; P1.3 53.18,16.5 ; P1.3 51.02,16.5 ; P1.3 52.1,15.42 ; P4.22 11.46,55.7 ; P4.22 12.54,54.62 ; P4.22 10.39,54.62 ; P4.22 11.46,53.54 ; 52.12,43.38 J2.2 ; J2.2 51.05,44.46 ; J2.2 53.2,44.46 ; J2.2 52.12,45.54 ; C15.2 25.78,12.9 v1(25.7,12.9) ; 44.29,26 44.3,26 ; v1(24.3,26.6) C31.2 ; C31.2 25,26.07 ; C31.2 25.52,26.6 ; C12.2 28.64,24.7 ; C12.2 28.12,24.2 ; C12.2 28.12,25.2 ; 5.32,16.5 P2.3 ; P2.3 6.4,17.58 ; P2.3 7.48,16.5 ; P2.3 6.4,15.42 ; v1(28.4,26.7) 28.5,26.8 C21.1 28.8,27.1 v1(29,27.1)
  TOP w0.3: v1(41.37,50.1) 41.6,50.1 41.97,49.73 P5.3 ; J6.5 12.7,88.18 13,87.88 13,87.3
  L2 w0.15: P2.2 6.4,15.04 ; P2.2 7.48,13.96 ; P2.2 6.4,12.88 ; P2.2 5.32,13.96 ; 11.46,53.54 P4.22 ; P4.22 11.46,55.7 ; P4.22 10.39,54.62 ; P4.22 12.54,54.62 ; P1.3 52.1,17.58 ; P1.3 53.18,16.5 ; P1.3 51.02,16.5 ; P1.3 52.1,15.42 ; 55.8,90.55 MH4.1 53.65,92.7 ; 51.02,13.96 P1.2 ; P1.2 53.18,13.96 ; P1.2 52.1,15.04 ; P1.2 52.1,12.88 ; MH5.1 3,58.7 ; MH5.1 1.9,57.6 ; MH5.1 3,56.5 ; MH5.1 4.1,57.6 ; 11.46,56.08 P4.21 ; P4.21 12.54,57.16 ; P4.21 11.46,58.24 ; P4.21 10.39,57.16 ; J2.2 53.2,44.46 ; J2.2 52.12,43.38 ; J2.2 51.05,44.46 ; J2.2 52.12,45.54 ; 4.65,92.7 MH3.1 2.5,90.55 ; 7.85,41.92 J1.4 ; J1.4 8.92,43 ; J1.4 8.92,40.84 ; J1.4 10,41.92 ; P2.3 7.48,16.5 ; P2.3 6.4,15.42 ; P2.3 5.32,16.5 ; P2.3 6.4,17.58
  BOTTOM w0.15: 51.02,16.5 P1.3 ; P1.3 52.1,17.58 ; P1.3 53.18,16.5 ; P1.3 52.1,15.42 ; 52.1,12.88 P1.2 ; P1.2 53.18,13.96 ; P1.2 51.02,13.96 ; P1.2 52.1,15.04 ; 57.42,94.32 MH4.1 57.91,93.61 ; P4.22 11.46,55.7 ; P4.22 10.39,54.62 ; P4.22 11.46,53.54 ; P4.22 12.54,54.62 ; 7.85,41.92 J1.4 ; J1.4 8.92,40.84 ; J1.4 8.92,43 ; J1.4 10,41.92 ; 5.32,13.96 P2.2 ; P2.2 6.4,12.88 ; P2.2 7.48,13.96 ; P2.2 6.4,15.04 ; J2.2 52.12,45.54 ; J2.2 52.12,43.38 ; J2.2 51.05,44.46 ; J2.2 53.2,44.46 ; P4.21 12.54,57.16 ; P4.21 11.46,56.08 ; P4.21 10.39,57.16 ; P4.21 11.46,58.24 ; P2.3 7.48,16.5 ; P2.3 6.4,17.58 ; P2.3 6.4,15.42 ; P2.3 5.32,16.5
  vias: v1(1.4,45.9) v1(1.5,67.7) v1(1.7,70.9) v1(1.7,41) v1(2,87.2) v1(2.1,84.5) v1(2.1,73.4) v1(2.2,74.4) v1(2.5,27.9) v1(2.5,16.8) v1(2.6,53.2) v1(3.6,61.7) v1(4.3,22.7) v1(4.5,82.4) v1(4.6,80.8) v1(5.2,86.7) v1(5.3,50.8) v1(5.4,71.1) v1(6.1,88) v1(6.1,77.7) v1(6.3,61.5) v1(7,54.1) v1(7.4,82.5) v1(8.9,88.4) v1(8.9,65.2) v1(9.2,19.2) v1(9.4,13) v1(10,52.9) v1(10,16.7) v1(10.1,84.2) v1(10.5,80.9) v1(10.9,84.9) v1(11.1,25.6) v1(11.32,62.1) v1(11.5,46) v1(11.6,78.1) v1(11.9,65.2) v1(12.2,12.9) v1(12.4,81.6) v1(12.6,29.3) v1(12.7,17.8) v1(13.4,41.4) v1(13.5,88.2) v1(13.7,87.4) v1(13.8,32.2) v1(13.8,24.3) v1(14.2,38.7) v1(14.5,20.3) v1(14.9,88.1) v1(15,13.1) v1(15.5,16.4) v1(15.9,87.2) v1(16.1,61.8) v1(16.4,32.6) v1(16.8,41.3) v1(16.9,29.3) v1(17.1,25.1) v1(17.3,78.1) v1(17.5,86.3) v1(17.5,61.4) v1(17.8,74.1) v1(17.8,71.4) v1(17.8,53) v1(17.9,77.7) v1(17.9,75.4) v1(17.9,47.5) v1(18,12.6) v1(18.2,14.9) v1(19.2,61.3) v1(19.6,85.4) v1(20.2,38.7) v1(20.3,59.8) v1(20.5,16.2) v1(20.6,19.7) v1(20.7,63.9) v1(20.7,53.6) v1(20.7,29.1) v1(20.8,12.5) v1(21,32.6) v1(21,24.8) v1(21.3,70.9) v1(21.5,87.6) v1(21.6,59.6) v1(21.9,22) v1(22.1,37.1) v1(22.3,85.1) v1(22.7,76.6) v1(22.7,74.7) v1(22.9,69.2) v1(22.9,30.8) v1(22.9,12.4) v1(23,15.5) v1(23.1,32.2) v1(23.5,30.3) v1(23.6,28.1) v1(23.7,32.6) v1(23.7,28.8) v1(23.82,12.3) v1(23.9,37.7) v1(23.9,19.2) v1(24.4,59.9) v1(24.9,63.6) v1(24.9,24.7) v1(24.9,16.9) v1(25,87.6) v1(25,26) v1(25,15.1) v1(25,12.4) v1(25.1,82.7) v1(25.1,78.1) v1(25.2,73.9) v1(25.7,26.6) v1(25.7,22.1) v1(25.8,65.8) v1(26,46.3) v1(26.1,19.3) v1(26.2,28.4) v1(26.3,22.8) v1(26.6,59.4) v1(26.7,39.8) v1(26.7,39.3) v1(27,52.9) v1(27.2,94) v1(27.2,39.8) v1(27.2,39.3) v1(27.3,67.9) v1(27.5,48) v1(28,13.7) v1(28.1,24.1) v1(28.1,17.7) v1(28.1,12.5) v1(28.2,25.4) v1(28.34,60.1) v1(28.3,19.6) v1(28.5,21.8) v1(28.5,13.1) v1(28.8,24.7) v1(29.3,42.9) v1(29.4,16.7) v1(29.7,23.5) v1(29.7,15) v1(29.7,12.8) v1(30.2,17.6) v1(30.3,63.8) v1(30.6,20) v1(31,48.5) v1(31.3,20.9) v1(31.7,16.6) v1(32.3,12.8) v1(32.5,20.4) v1(33,62.4) v1(33.2,24.7) v1(33.2,16.8) v1(33.6,58.68) v1(33.6,36.5) v1(33.6,19.2) v1(33.7,42.9) v1(33.7,17.9) v1(34,37.2) v1(34.2,48.3) v1(34.6,42.4) v1(34.9,33.8) v1(34.9,30.3) v1(35.1,45.7) v1(35.1,21.4) v1(35.4,24.5) v1(35.4,14.5) v1(35.5,35.2) v1(35.6,29.68) v1(35.9,64.1) v1(36,41.5) v1(36.1,12.7) v1(36.4,93.7) v1(36.8,50) v1(37.2,80.9) v1(37.5,23.82) v1(37.5,16.8) v1(39,62.9) v1(39,12.7) v1(39.2,20) v1(39.5,59.6) v1(39.6,24.7) v1(39.6,23.1) v1(40.1,51.4) v1(40.2,15.1) v1(40.5,64.9) v1(40.9,27.3) v1(41.6,56.4) v1(41.6,17.5) v1(42.4,41.6) v1(42.5,93.8) v1(42.5,59.2) v1(42.5,35.9) v1(42.5,14.4) v1(42.6,50) v1(43.2,12.6) v1(43.3,51.9) v1(43.8,62.2) v1(44.3,38.5) v1(44.4,28.5) v1(44.8,65.1) v1(44.8,44.8) v1(44.8,25.3) v1(45.2,50.8) v1(45.2,31.2) v1(45.4,27.4) v1(45.6,17.2) v1(45.8,22.8) v1(45.9,15.1) v1(46.2,19.9) v1(46.4,12.5) v1(47.1,42.7) v1(47.3,49.5) v1(47.3,36.2) v1(47.5,33.7) v1(47.8,29.8) v1(48,53.9) v1(48.9,12.5) v1(49.1,62.8) v1(49.6,93.5) v1(49.7,16.2) v1(50.2,51.9) v1(50.4,46.6) v1(51,22.8) v1(51.1,28.5) v1(52.8,51.8) v1(53,65.4) v1(53.3,50.6) v1(53.9,61.4) v1(53.9,35) v1(54,23.4) v1(54.6,28) v1(54.9,12.8) v1(55.6,18) v1(56.1,55.4) v1(56.4,71.4) v1(56.5,65.4) v1(56.6,78.8) v1(56.7,82.8) v1(56.8,87.6) v1(56.9,25.1) v1(57.1,39.2) v1(57.6,45.5) v2(27.6,34.6) v2(27.6,33.6) v2(27.6,32.6) v2(27.6,31.6) v2(27.6,30.6) v2(28.6,34.6) v2(28.6,33.6) v2(28.6,32.6) v2(28.6,31.6) v2(28.6,30.6) v2(29.6,34.6) v2(29.6,33.6) v2(29.6,32.6) v2(29.6,31.6) v2(29.6,30.6) v2(30.6,34.6) v2(30.6,33.6) v2(30.6,32.6) v2(30.6,31.6) v2(30.6,30.6) v2(31.6,34.6) v2(31.6,33.6) v2(31.6,32.6) v2(31.6,31.6) v2(31.6,30.6)
VDDC: length 16.2
  TOP w0.2: U5.87 8.9,72.2 7.3,70.6 U5.115 2.5,70.6 C43.1 C44.1 C45.1
VDDR: length 37.3
  TOP w0.3: U1.45 25.12,31.32 C16.1 24.6,30.9 24.07,31.43 19.53,31.43 19.2,31.1 19.2,27.3 19.5,27 23.45,27 25.1,28.65 C9.1 25.65,28.8 26.18,29.32 U1.48
  TOP w0.4: v1(22.7,33.1) 22.3,32.7 22.3,31.63 22.1,31.43 ; v1(23,36.5) 23,40.7 24.1,41.8 27.43,41.8 28.4,40.82 C8.1 L1.2
  L3 w0.4: v1(22.7,33.1) 22.7,35.67 23,35.97 v1(23,36.5)
VDDS: length 43.7
  TOP w0.2: v1(34.2,30.3) C3.1
  TOP w0.3: U1.34 27.9,36.73 27,37.63 ; C4.1 34.3,34.73 34.9,35.33 34.9,37.28 34.04,38.14 34.04,38.16 v1(33.7,38.5) ; C4.1 34.3,33.7 v1(34.22,33.62) ; C4.1 34.12,34.32 U1.22 ; 27,37.63 C7.1 ; 27,37.63 27,37.57 26.87,37.7 C6.1 ; C3.1 34.08,29.82 U1.13 ; v1(24.4,42.5) 28.1,42.5 29.4,41.2 29.4,38.9 v1(29.2,38.7) ; v1(24.4,32.7) 24.6,32.5 C5.1 25.15,32 25.33,31.82 U1.44 ; 24.8,37.7 24.9,37.6 R1.2 24.9,37
  TOP w0.4: C6.1 24.8,37.7 v1(24.4,38.1) v1(24.4,41.25)
  TOP w0.5: FL1.1 v1(24.4,42.5)
  L3 w0.2: v1(34.2,30.3) 34.2,33.17 34.22,33.19 v1(34.22,33.62)
  L3 w0.3: v1(24.4,32.7) v1(24.4,38.1) ; v1(33.7,38.5) 29.88,38.5 29.68,38.7 v1(29.2,38.7)
  L3 w0.4: v1(24.4,41.25) v1(24.4,42.5)
BP_RESET: length 21.2
  TOP w0.15: J2.11 48.07,31.76 46.93,32.9 46.93,32.9 46.32,33.5 42.7,33.5 41.1,35.1 41.1,38.8 41.44,39.15 41.44,39.56 41.3,39.7 41.3,39.7 41.1,39.9 41.1,43.32 42.6,44.82 R52.2
CC2650_RESET: length 69.7
  TOP w0.15: v1(41.4,47.9) 42.2,47.1 R52.1 R51.2 45.24,47.1 46.6,48.46 46.6,50.83 45.78,51.65 P5.10 ; v1(25.4,49.2) 27.9,49.2 29.2,47.9 29.2,45.97 29.3,45.88 29.3,45.45 28.55,44.7 20.5,44.7 19.1,43.3 19.1,36.7 19.72,36.07 23.18,36.07 23.3,36.2 C20.1 R1.1 25.7,36.2 26.17,36.67 27.06,36.67 27.4,36.33 U1.35 ; CR8.2 v1(38.6,49.8)
  L3 w0.15: v1(41.4,47.9) 39.5,49.8 v1(38.6,49.8) 37.2,49.8 36.98,49.57 35.28,49.57 35.18,49.47 30.05,49.47 29.2,50.32 26.53,50.32 v1(25.4,49.2) 25.4,53.38 P4.12
CC2650_RXD: length 92
  TOP w0.15: v1(28.6,49.9) 28.2,49.9 28,50.1 10.54,50.1 5,44.56 5,38.22 J1.7 ; U1.7 29.9,28.59 31.22,27.28 33.53,27.28 33.95,27.7 36.72,27.7 39.9,30.88 39.9,45.5 40.6,46.2 40.6,46.5 38.43,48.67 v1(37.7,48.67)
  L3 w0.15: P4.16 20.26,55.8 22.4,55.8 22.9,55.3 22.9,51.1 25.22,48.78 27.47,48.78 v1(28.6,49.9) 29,49.9 29,49.9 29.2,49.9 29.93,49.18 35.3,49.18 35.31,49.19 37.19,49.19 v1(37.7,48.67)
CC2650_SWO: length 45.8
  TOP w0.15: U1.28 30.9,36.72 31.07,36.9 31.07,40.22 31.25,40.4 v1(31.25,40.8) 31.25,41.5 31.6,41.85 31.6,46.15 31.75,46.3 31.75,51.85 31.6,52 v1(31.6,52.4)
  L3 w0.15: v1(31.25,40.8) 31.97,41.53 33.57,41.53 38.6,36.5 42.5,36.5 42.93,36.08 42.93,35.23 43.85,34.3 J2.9 ; v1(31.6,52.4) 31.9,52.1 35.1,52.1 36.86,53.86 P4.2
CC2650_TCK: length 61.5
  TOP w0.15: U1.25 32.4,36.8 32.6,37 v1(32.6,41.1) 32.6,41.5 32.7,41.6 32.7,51.2 v1(33,51.5) 34.28,52.78 37.57,52.78 39.75,54.95 41.47,54.95 41.97,54.45 P5.4 41.97,52.95 41.22,52.2 39.9,52.2 39.4,52.7 38.8,52.7 38.6,52.5 CR8.6 ; v1(44.6,32) 44.6,30.4 44.13,29.93 42.73,29.93 42.6,29.79 42.6,28.4 41.7,27.5 R47.2
  L3 w0.15: P4.8 29.97,53.89 29.97,53.23 31.7,51.5 v1(33,51.5) ; v1(44.6,32) 44.6,33.1 42.5,35.2 39.4,35.2 33.5,41.1 v1(32.6,41.1)
CC2650_TMS: length 54
  TOP w0.15: P5.2 39.2,53.7 38.1,52.6 CR8.7 v1(35.7,51.9) 34.7,51.9 33.13,50.32 v1(33.13,40.3) U1.24 ; R46.2 41.7,29.9 43.7,31.9 v1(43.7,32.2)
  L3 w0.15: P4.10 27.75,53.57 29.2,53.57 31.7,51.07 33.18,51.07 33.38,51.27 35.07,51.27 v1(35.7,51.9) ; v1(33.13,40.3) 33.53,40.3 38.2,35.63 38.2,34.95 38.35,34.8 42.3,34.8 43.7,33.4 v1(43.7,32.2)
CC2650_TXD: length 76.8
  TOP w0.15: v1(21.62,49.68) 21.62,49.78 ; 21.62,49.78 21.6,49.8 10.7,49.8 7.46,46.56 7.46,43.96 6.8,43.3 5.8,43.3 5.3,42.8 5.3,40.46 J1.5 ; 21.62,49.78 21.7,49.7 27.87,49.7 28.27,49.3 v1(29.07,49.3) ; U1.8 30.4,28.52 31.34,27.57 33.4,27.57 33.82,28 36.6,28 39.6,31 39.6,46.63 v1(38.26,47.96)
  L3 w0.15: v1(38.26,47.96) 37.34,47.96 36.5,48.8 31.9,48.8 31.18,48.07 30.3,48.07 v1(29.07,49.3) ; P4.14 v1(21.62,49.68)
CC2650_VDD: length 179.4
  TOP w0.15: 2.75,19.25 3.35,18.65 v1(2.75,18.05)
  TOP w0.3: v1(40.7,47.3) P5.1 38.3,49.1 37.4,50 37.4,50.7 CR8.8 ; v1(36.4,21.2) 36.4,22.08 R59.2 36.4,22.12 R11.2
  TOP w0.4: v1(35.4,25.5) 35.5,25.6 C30.1 36.2,25.5 36.8,25.5 ; 36.8,25.5 U4.8 ; 36.8,25.5 36.78,25.52 R60.2
  TOP w0.5: v1(20.7,42.5) FL1.2
  L3 w0.3: v1(36.4,21.2) 38.8,21.2 40.56,22.96 ; P1.1 40.56,22.96 ; 40.56,22.96 38.02,25.5 v1(35.4,25.5)
  L3 w0.5: P10.3 48.5,53.22 48.5,49.7 46.1,47.3 ; 46.1,47.3 51.9,47.3 57.75,41.45 57.75,17.07 P1.1 ; 46.1,47.3 v1(40.7,47.3) 25.5,47.3 v1(20.7,42.5) 18.89,42.5 18.19,43.2 16.7,43.2 ; P4.18 16.54,43.36 16.7,43.2 ; 16.7,43.2 7.64,43.2 J1.1 1.9,39.98 1.9,18.9 v1(2.75,18.05)
DCDC_SW: length 1.9
  TOP w0.3: L1.1 28.4,37.55 28.4,37.55 U1.33
DIO0: length 80.7
  TOP w0.15: v1(10.8,33) 10.8,32.6 10.6,32.4 10.6,27.9 10,27.3 10,26.25 8.92,25.17 J1.18 ; v1(28.7,45.6) 20.3,45.6 18.5,43.8 18.5,37.35 18.35,37.2 12.5,37.2 12.01,37.69 11.49,37.69 v1(11.2,37.4) ; U1.5 28.9,28.74 30.97,26.68 33.78,26.68 34.2,27.1 36.97,27.1 40.5,30.62 40.5,43.93 40.91,44.34 40.91,44.91 v1(40.62,45.2)
  L3 w0.15: v1(40.62,45.2) 29.5,45.2 29.1,45.6 v1(28.7,45.6) ; v1(10.8,33) 10.8,37 v1(11.2,37.4)
DIO1: length 84.1
  TOP w0.15: v1(11.3,33.5) 11.3,32.6 10.9,32.2 10.9,27.7 10.3,27.1 10.3,22.98 J1.20 ; v1(28.4,45.15) 20.35,45.15 18.8,43.6 18.8,37.2 18.5,36.9 12.3,36.9 12.1,37.1 v1(11.7,37.1) ; U1.6 29.4,28.67 31.09,26.97 33.65,26.97 34.07,27.4 36.85,27.4 40.2,30.75 40.2,44.05 40.6,44.45 40.6,44.62 40.45,44.78 40.45,44.78 40.2,45.02 40.2,45.38 40.6,45.78 v1(41,45.78)
  L3 w0.15: v1(11.7,37.1) 11.3,36.7 v1(11.3,33.5) ; v1(28.4,45.15) 28.95,45.15 29.4,44.7 41,44.7 41.28,44.99 41.28,45.49 v1(41,45.78)
DIO4_SCL: length 94.4
  TOP w0.15: v1(34.8,50.42) 35.2,50.42 39.3,46.32 39.3,31.12 36.47,28.3 33.7,28.3 33.28,27.88 31.47,27.88 30.9,28.44 U1.9 ; R2.1 5.3,21.8 5.3,23.06 J1.17 3.5,27.02 3.5,45.1 3.5,45.35 9.75,51.6 29.6,51.6 30.4,50.8 v1(30.9,50.8)
  L3 w0.15: v1(34.8,50.42) 31.08,50.42 30.9,50.6 v1(30.9,50.8)
DIO5_SDA: length 93.8
  TOP w0.15: v1(35,49.9) 39,45.9 39,31.25 36.35,28.6 33.57,28.6 33.15,28.18 31.59,28.18 31.4,28.37 U1.10 ; v1(30.87,50.05) 30.59,50.34 30.19,50.34 29.22,51.3 9.88,51.3 3.8,45.22 3.8,27.2 5.8,25.2 6.81,25.2 7.5,24.51 7.5,22.72 J1.19 4.42,19.64 4.34,19.64 R3.1
  L3 w0.15: v1(30.87,50.05) 31.27,50.05 31.42,49.9 v1(35,49.9)
DIO6_RLED: length 78.5
  TOP w0.15: U1.11 31.9,28.82 32.24,28.47 33.03,28.47 33.45,28.9 36.22,28.9 38.68,31.35 38.68,32.15 38.7,32.18 38.7,41.05 38.5,41.25 v1(38.5,44.2)
  L3 w0.15: J2.3 50.63,42.97 50.63,44.97 50,45.6 49.2,45.6 47.8,44.2 v1(38.5,44.2) 23.1,44.2 18.85,39.95 18.85,23.85 P6.2
DIO7_GLED: length 70
  TOP w0.15: U1.12 32.75,29.1 32.85,29.2 36.1,29.2 38.38,31.47 38.38,32.28 38.4,32.3 38.4,40.93 38.03,41.3 v1(38.03,43.6)
  L3 w0.15: P6.4 19.15,39.75 23.28,43.88 37.74,43.88 v1(38.03,43.6) 48.72,43.6 J2.1
DIO8_MISO: length 28.9
  TOP w0.15: U1.14 33.41,30.32 33.88,30.8 v1(37,30.8) ; v1(40.7,28.5) 40.2,28.5 39.07,27.38 39.07,24 38.68,23.6 38.05,23.6 37.7,23.25 U4.2
  L3 w0.15: J2.14 52.12,28.19 51.83,27.9 41.2,27.9 40.99,28.12 40.99,28.22 v1(40.7,28.5) 38.4,30.8 v1(37,30.8)
DIO9_MOSI: length 26.5
  TOP w0.15: U1.15 33.43,30.82 33.82,31.22 37.43,31.22 v1(37.7,31.5) ; U4.5 38.7,27.5 41.7,30.5 v1(41.7,30.6)
  L3 w0.15: v1(37.7,31.5) 40.3,31.5 41.2,30.6 v1(41.7,30.6) 50.96,30.6 J2.12
DIO10_SCLK: length 86.7
  TOP w0.15: v1(37.7,46.3) 37.99,46.01 37.99,45.43 37.6,45.05 37.6,41.3 38.1,40.8 38.1,32.6 v1(37.6,32.1) 37.03,31.53 33.7,31.53 33.5,31.32 U1.16 ; v1(30,46.7) 30,47.1 30,47.1 30,49.6 28.9,50.7 10.2,50.7 4.4,44.9 4.4,31.2 J1.13 ; v1(41.4,31.2) 41.1,30.9 41.1,30.38 38.25,27.53 38.25,25.79 38.2,25.74 U4.6
  L3 w0.15: v1(41.4,31.2) 40.5,32.1 38,32.1 v1(37.6,32.1) ; v1(37.7,46.3) 37.3,46.3 37.2,46.2 30.5,46.2 30.29,46.41 30.29,46.41 v1(30,46.7)
DIO11_CS: length 27.8
  TOP w0.15: v1(37.6,40.5) 37.6,40.1 37.8,39.9 37.8,32.9 36.72,31.82 U1.17
  L3 w0.15: v1(37.6,40.5) 51,40.5 J2.6
DIO12: length 35.6
  TOP w0.15: U1.18 33.5,32.33 33.62,32.2 36.6,32.2 37.5,33.1 37.5,39.7 37.1,40.1 37.1,40.7 37.3,40.9 37.3,45.17 37.43,45.3 v1(37.43,45.7)
  L3 w0.15: v1(37.43,45.7) 40.1,45.7 40.6,46.2 41.7,46.2 42,45.9 50.3,45.9 50.93,45.27 50.93,43.11 J2.4
DIO13_BTN1: length 78.3
  TOP w0.15: v1(30.7,51.4) 30.2,51.9 9.62,51.9 6.43,48.7 R56.2 5.9,48.7 ; U1.19 33.42,32.83 33.55,32.7 33.6,32.7 33.8,32.5 36.44,32.5 36.9,32.96 v1(36.9,33.36) 37.2,33.66 37.2,39.5 36.8,39.9 36.8,40.9 37,41.1 37,47.2 34.25,49.95 v1(34.25,50.85)
  L3 w0.15: v1(30.7,51.4) 30.95,51.4 31.57,50.78 33.3,50.78 33.38,50.85 v1(34.25,50.85) ; J2.16 53.8,28.36 53.8,32.1 53,32.9 47.4,32.9 46.08,31.58 45.43,31.58 45.38,31.62 45.02,31.62 44.97,31.58 43.72,31.58 42.42,32.88 41.82,32.88 41.34,33.36 v1(36.9,33.36)
DIO14_BTN2: length 54.3
  TOP w0.15: U1.20 33.48,33.32 34.01,32.8 35.93,32.8 36.06,32.94 36.3,32.94 36.3,32.95 v1(36.29,32.95) ; v1(55.9,24.2) 55.9,24.6 55.7,24.8 55.7,44.99 56.81,46.1 R55.2 ; v1(41.5,32.4) 41.9,32.8 46.18,32.8 48.68,30.3 52.53,30.3 53.2,29.63 53.2,25.22 J2.18
  L3 w0.15: v1(55.9,24.2) 55.5,24.2 55.44,24.14 J2.18 ; v1(41.5,32.4) 41.1,32.8 36.84,32.8 36.69,32.95 v1(36.29,32.95)
DIO15: length 31.6
  TOP w0.15: v1(36.78,34) 36.37,34 35.47,33.1 34.13,33.1 33.41,33.82 U1.21 ; v1(42,33.31) 42.4,33.31 42.41,33.3 42.43,33.3 42.63,33.1 46.3,33.1 48.7,30.7 52.6,30.7 53.5,29.8 53.5,22.98 J2.20
  L3 w0.15: v1(42,33.31) 41.72,33.59 41.71,33.59 41.27,34.03 40.9,34.03 40.87,34 v1(36.78,34)
DIO16_TDO: length 58.1
  TOP w0.15: R48.2 41.7,25 v1(40.7,26) ; U1.26 31.9,36.73 32.1,36.93 v1(32.1,39.8) 32.1,41.43 32.4,41.73 32.4,52.7 P4.4 35.05,53.89 35.05,53.75 35.72,53.07 37.45,53.07 39.68,55.3 42.87,55.3 43.24,54.93 P5.6 43.24,52.95 42.19,51.9 CR8.5
  L3 w0.15: v1(40.7,26) 40.7,26.4 35.5,31.6 35.5,33.37 36.5,34.37 36.5,36.73 33.43,39.8 v1(32.1,39.8)
DIO17_TDI: length 66.3
  TOP w0.15: U1.27 31.4,36.65 31.6,36.85 31.6,39.1 31.5,39.2 v1(31.5,39.6) 31.5,40 31.68,40.18 31.68,41.43 32.1,41.85 32.1,52.9 31.78,53.22 P4.6 32.86,55.7 v1(38.2,55.7) ; R49.2 41.8,22.3 40.2,23.9 v1(40.2,25.5) ; CR8.3 39.45,50.4 39.65,50.6 43.4,50.6 44.51,51.71 P5.8 v1(44.51,55.78)
  L3 w0.15: v1(38.2,55.7) 39.72,55.7 39.8,55.78 v1(44.51,55.78) ; v1(40.2,25.5) 40.2,26.2 35.1,31.3 35.1,33.4 36,34.3 36,36.8 33.88,38.93 32.18,38.93 v1(31.5,39.6)
DIO19_CTS: length 26.9
  TOP w0.15: v1(30.95,41.8) 30.95,41.4 30.78,41.22 30.78,37.18 30.4,36.8 U1.29
  L3 w0.15: J2.7 38.86,36.84 33.62,42.09 31.24,42.09 v1(30.95,41.8)
DIO20_FLASH_CS: length 59.6
  TOP w0.15: v1(31,46.7) 31,42.8 30.47,42.28 30.47,37.45 30.3,37.28 30.3,37.2 29.9,36.8 U1.30 ; v1(41.2,46.7) 41.5,46.4 41.5,44.5 40.8,43.8 40.8,39.4 ; 40.8,39.4 40.8,30.5 37.1,26.8 35.4,26.8 34.5,25.9 34.5,24.5 35.1,23.9 R11.1 36.4,23.9 36.81,23.48 36.82,23.48 U4.1 ; 40.8,39.4 40.82,39.38 v1(41.02,39.38)
  L3 w0.15: v1(41.2,46.7) 37.9,46.7 37.88,46.72 31.43,46.72 31.4,46.7 v1(31,46.7) ; J2.5 v1(41.02,39.38)
DIO21: length 62.8
  TOP w0.15: U1.31 29.4,36.8 30.18,37.57 30.18,46.07 30.47,46.38 30.47,49.62 29.1,51 10,51 4.1,45.1 4.1,28.96 J1.15
DIO22: length 52.7
  TOP w0.15: J1.9 4.7,35.98 4.7,44.7 10.4,50.4 28.7,50.4 29.5,49.6 29.5,46.1 29.88,45.72 29.88,37.7 28.9,36.72 U1.32
DIO23_ANALOG: length 24.7
  TOP w0.15: J1.3 7.5,40.8 9.5,40.8 10.6,39.7 10.6,37.2 11.2,36.6 18.6,36.6 19.5,35.7 25.62,35.7 25.97,36.05 U1.36
DIO24_ANALOG: length 30.8
  TOP w0.15: U1.37 25.57,35.33 25.5,35.4 19.3,35.4 18.4,36.3 11,36.3 10.3,37 10.3,39.5 9.37,40.43 8.43,40.43 7.8,39.8 7.8,33.18 J1.11
DIO25_ANALOG: length 20
  TOP w0.15: J1.6 10,38.3 10,36.8 10.8,36 18.2,36 19.1,35.1 25.3,35.1 25.4,35 25.57,34.82 U1.38
DIO26_ANALOG: length 18.3
  TOP w0.15: J1.8 10.06,35.7 18,35.7 18.9,34.8 25.1,34.8 25.57,34.32 U1.39
DIO27_ANALOG: length 18.3
  TOP w0.15: J1.10 9.95,35.33 17.87,35.33 18.7,34.5 24.9,34.5 25.57,33.82 U1.40
DIO28_ANALOG: length 19.9
  TOP w0.15: J1.12 8.92,32.79 11.16,35.03 17.67,35.03 18.5,34.2 24.7,34.2 25.57,33.32 U1.41
DIO29_ANALOG: length 22.1
  TOP w0.15: J1.14 8.92,30.25 10,31.32 10,33.4 11.33,34.73 17.47,34.73 18.3,33.9 24.5,33.9 25.57,32.83 U1.42
DIO30_ANALOG: length 24.3
  TOP w0.15: J1.16 10.3,28.06 10.3,33.2 11.53,34.43 17.27,34.43 18.1,33.6 24.3,33.6 25.57,32.33 U1.43
IRSTN: length 16.5
  TOP w0.15: v1(5.3,85.5) 5.3,83.9 v1(3.5,82.1) ; 14.4,80.9 R20.2 11.8,80.9 11.2,81.5 11.2,83.8 9.5,85.5 v1(6.82,85.5)
  L3 w0.15: v1(5.3,85.5) v1(6.82,85.5)
ITCK: length 12.2
  TOP w0.15: U5.100 2,76.6 0.8,77.8 0.8,84.7 v1(2.1,86)
ITDI: length 10.1
  TOP w0.15: v1(3.38,84.7) 2.8,84.12 2.8,82.5 1.44,81.14 1.44,78.01 2.05,77.4 U5.98
ITDO: length 13.2
  TOP w0.15: U5.97 2.08,77.8 1.74,78.14 1.74,81.01 4.8,84.08 4.8,85.9 v1(3.4,87.3)
ITMS: length 9
  TOP w0.15: v1(2.1,83.5) 1.14,82.54 1.14,77.89 2.03,77 3.8,77
LP_RESET: length 23.7
  TOP w0.15: J2.10 51.02,33.2 47.05,33.2 46.45,33.8 42.83,33.8 41.41,35.21 41.41,38.61 41.75,38.94 41.75,39.68 41.4,40.03 41.4,42.93 43.97,45.5 R51.1
USB_DM: length 14.1
  TOP w0.15: v1(8.7,86.9) 7.3,86.9 6.4,86 6.4,80.1 6.5,80 U5.93 ; J6.2 v1(10.75,88.9) 10.8,88.85 CR6.5
  L3 w0.15: v1(10.75,88.9) 10.75,88.88 9.06,87.19 8.99,87.19 v1(8.7,86.9)
USB_DP: length 15.5
  TOP w0.15: v1(9.4,86.9) 8.91,87.38 7.36,87.38 6.1,86.12 U5.94 ; 11.3,88.19 11.3,88.8 v1(11.4,88.9) J6.3
  L3 w0.15: v1(9.4,86.9) v1(11.4,88.9)
USB_ID: length 14.1
  TOP w0.15: CR6.2 v1(10.8,87) 10.1,87 9.4,87.7 7.25,87.7 5.8,86.25 5.8,82.7 R67.1 ; J6.4 v1(12.05,88.9)
  L3 w0.15: v1(10.8,87) 10.8,87.65 v1(12.05,88.9)
USB_VBUS: length 55.4
  TOP w0.15: R22.2 4.38,62.78 4.6,63 v1(4.6,63.1) ; U7.8 v1(14.7,86.58)
  TOP w0.2: R66.1 3.4,80.1 v1(2.6,79.3)
  TOP w0.3: U7.2 U7.1 11.7,86.58 12.2,87.08 C48.1 ; CR6.6 10.3,88.67 10.1,88.87 v1(10.1,88.9) J6.1
  TOP w0.5: v1(12.2,87.9) C48.1
  L3 w0.5: 0.75,79.4 0.85,79.3 v1(2.6,79.3) ; 0.75,79.4 0.75,66.95 v1(4.6,63.1) 4.6,62.35 8.57,58.38 12.78,58.38 P4.19 ; 0.75,79.4 0.75,84.24 1.85,85.34 3.24,85.34 4,86.1 11.22,86.1
V-SENSE: length 41.2
  TOP w0.15: U10.2 C55.1 v1(25.7,61.1) ; v1(29.7,61.1) C57.1
  TOP w0.3: P10.2 48.3,58.76 48.3,60.55 46.31,62.53 P7.1 45.76,63.28 45.14,63.9 38.1,63.9 36.2,62 ; C57.1 U9.2 ; 36.2,62 35.3,61.1 v1(29.7,61.1) ; 36.2,62 38.15,62 38.55,61.6 CR7.8 ; U8.2 C53.1 v1(21.7,61.1)
  L3 w0.3: v1(29.7,61.1) 27.6,61.1 27.5,61 27.09,61 26.99,61.1 v1(25.7,61.1) v1(21.7,61.1)
XDS_RESET: length 11.4
  TOP w0.15: v1(23.51,63.7) U10.6 23.51,60.97 23.78,60.7 U10.1 ; U5.40 21.2,68.2 R58.1 21.3,68.1 21.8,67.6 21.8,66.7 v1(22.8,65.7)
  L3 w0.15: v1(22.8,65.7) 23.5,65.7 23.79,65.4 23.79,63.99 v1(23.51,63.7)
XDS_RESET_LS: length 66.7
  TOP w0.15: CR7.2 37.2,60.6 36.71,60.11 ; U10.15 23.51,58.99 v1(23.75,58.75) 24.16,58.34 P4.11 ; 36.71,60.11 36.32,60.5 v1(33.9,60.5) ; 36.71,60.11 36.71,59.59 38.37,57.93 40.68,57.93 ; v1(17,90.3) R57.2
  L3 w0.15: 33.5,60.5 33.47,60.52 27.12,60.52 25.35,58.75 v1(23.75,58.75) ; 33.5,60.5 30.45,60.5 30.3,60.65 30.3,62 27.7,64.6 24.35,64.6 24.2,64.75 24.2,86.5 20.4,90.3 v1(17,90.3) ; 33.5,60.5 v1(33.9,60.5)
XDS_RX: length 3.1
  TOP w0.15: U8.8 18.71,62.84 19.2,63.33 U5.33
XDS_RX_LS: length 8
  TOP w0.15: U8.13 18.71,59.41 R61.2 18.82,58.45 18,57.62 18,56.76 18.65,56.11 20.57,56.11 P4.13
XDS_SWO: length 7.2
  TOP w0.15: U8.9 18.1,62.3 18.1,64.75 17.95,64.9 15.05,64.9 14.9,64.75 U5.25
XDS_SWO_LS: length 25.3
  TOP w0.15: v1(33.6,59.8) 35.6,59.8 36.5,58.9 ; 36.5,58.9 R62.2 35.5,58.9 ; 36.5,58.9 36.86,58.54 P4.1 ; U8.12 v1(17.7,60.7)
  L3 w0.15: v1(17.7,60.7) 17.7,59.4 18.89,58.21 26.21,58.21 27.5,59.5 32.9,59.5 33.2,59.8 v1(33.6,59.8)
XDS_TCK: length 10.4
  TOP w0.15: v1(23.3,65.2) 23.69,64.81 25.78,64.81 27.51,63.09 U9.6 ; v1(20.7,65.2) 20.7,65.65 20.15,66.2 U5.35
  L3 w0.15: v1(23.3,65.2) v1(20.7,65.2)
XDS_TCK_LS: length 31.7
  TOP w0.15: v1(35.9,53.5) 37.3,53.5 39.57,55.77 43.59,55.77 44.49,56.67 P7.4 44.49,60.21 44.1,60.6 CR7.6 ; U9.15 27.51,59.65 27.66,59.5 28.09,59.5 29.24,58.34 P4.7
  L3 w0.15: P4.7 30.73,55.67 35.23,55.67 35.62,55.28 35.62,53.78 v1(35.9,53.5)
XDS_TDI: length 10.2
  TOP w0.15: U5.38 20.25,67.4 23.15,64.5 25.66,64.5 27.11,63.05 U9.7
XDS_TDI_LS: length 26.4
  TOP w0.15: U9.14 27.11,59.55 27.66,59 27.9,59 28.1,58.8 28.1,56.7 28.69,56.11 30.73,56.11 P4.5 32.84,56.1 37.29,56.1 37.39,56.2 40.6,56.2 41.3,56.9 41.3,57.76 41.47,57.93 P7.8 41.95,59.16 41.71,59.4 40.3,59.4 40,59.1 38.43,59.1 37.8,59.73 CR7.3
XDS_TDO: length 10.1
  TOP w0.15: 19.2,67 20.23,67 23.03,64.2 25.4,64.2 26.3,63.3 26.3,62.1 U9.9
XDS_TDO_LS: length 26.2
  TOP w0.15: CR7.5 v1(40.5,60.1) 40.9,60.1 41.1,60.3 42.6,60.3 43.2,59.7 43.2,57.95 P7.6 43.22,57.93 R63.2 ; v1(27.65,58.53) 26.77,58.53 26.03,59.27 26.03,60.46 26.27,60.7 U9.12
  L3 w0.15: v1(40.5,60.1) 40.5,59.7 39.5,58.7 35.86,58.7 P4.3 32.95,58.53 v1(27.65,58.53)
XDS_TMS: length 6.1
  TOP w0.15: U5.36 20.2,66.6 22.71,64.09 U10.8
XDS_TMS_DIR: length 12.8
  TOP w0.15: U10.5 23.91,63.11 v1(24,63.2) ; v1(18.6,63.5) 18.6,64.68 18.07,65.2 14.85,65.2 14.5,64.85 U5.24
  L3 w0.15: v1(18.6,63.5) 18.9,63.2 v1(24,63.2)
XDS_TMS_LS: length 34
  TOP w0.15: P4.9 25.64,56.1 23.4,56.1 22.71,56.79 U10.13 ; CR7.7 v1(40,61.1) 45.4,61.1 45.76,60.74 P7.2 46.29,57.93 46.35,57.88 R65.2
  L3 w0.15: v1(40,61.1) 35.8,61.1 34.32,59.62 33.8,59.1 27.62,59.1 26.7,58.19 P4.9
XDS_TX: length 4.5
  TOP w0.15: U8.6 19.51,64.51 20.2,65.2 20.2,65.65 20.05,65.8 U5.34
XDS_TX_LS: length 3.1
  TOP w0.15: U8.15 19.51,58.71 19.08,58.28 P4.15
XDS_VCC: length 87.6
  TOP w0.15: v1(25.7,61.9) C54.1 U10.4 ; v1(8.9,60.9) R18.2 8.45,61.58 8.42,61.6 C42.1 ; v1(1.75,76) C37.1 2.6,76.2 U5.101 ; v1(1.7,71.5) C36.1 ; U5.122 v1(5.2,67.8) ; C38.1 16.21,80.9 16.6,81.29 16.6,81.39 17.11,81.9 R17.2 17.12,82.62 v1(17.1,82.65) ; R58.2 21.23,67.18 v1(20.7,67.7) ; R33.2 16.72,85.02 C47.1 v1(16.6,85.5) ; U8.3 U8.4 ; R30.2 v1(22.5,75.7) ; v1(29.7,61.9) C56.1
  TOP w0.2: 19.2,71 v1(20.26,71) ; v1(11.5,62.82) 11.3,63.02 U5.16 ; U5.52 U5.51 C39.1 C40.1 v1(22.5,72.6) ; v1(21.9,79) R39.1 R27.1 ; v1(7.6,80.4) 7.7,80.3 U5.90 ; U9.3 U9.4 ; 15.5,62.5 C35.1 v1(15.5,61.85) ; 15.5,62.5 16.1,63.1 U5.28 ; 15.5,62.5 15.3,62.7 U5.26 ; v1(5,71.7) 4.7,71.4 U5.113 2.4,71.4 C36.1 ; 16.2,80.94 C38.1 16.2,80.45 16.1,80.35 U5.69 ; 20,80.9 R31.2 v1(20.6,80.9) ; U5.122 v1(2.74,67.8) ; U5.39 20.6,67.8 v1(20.7,67.7) ; U5.7 U5.8 8.1,62.7 C41.1 C42.1 ; U5.79 v1(12.1,80.36) ; U10.3 U10.4
  TOP w0.3: v1(29.7,61.9) 35.1,61.9 37.6,64.4 46.7,64.4 49.9,61.2 P10.1 ; v1(21.7,61.9) C52.1 U8.4 ; P4.17 15.5,58.2 v1(15.5,61.85) ; C56.1 U9.4 ; v1(11.7,82.3) C49.1 U7.4 U7.3
  L3 w0.3: v1(29.7,61.9) 27.6,61.9 27.5,62 27.09,62 26.99,61.9 v1(25.7,61.9) v1(21.7,61.9) 19.2,61.9 17.6,63.5
  L3 w0.5: v1(16.6,85.5) 16.6,83.1 ; 15.2,61.2 15.23,61.2
  vias: v1(2,82.4)
